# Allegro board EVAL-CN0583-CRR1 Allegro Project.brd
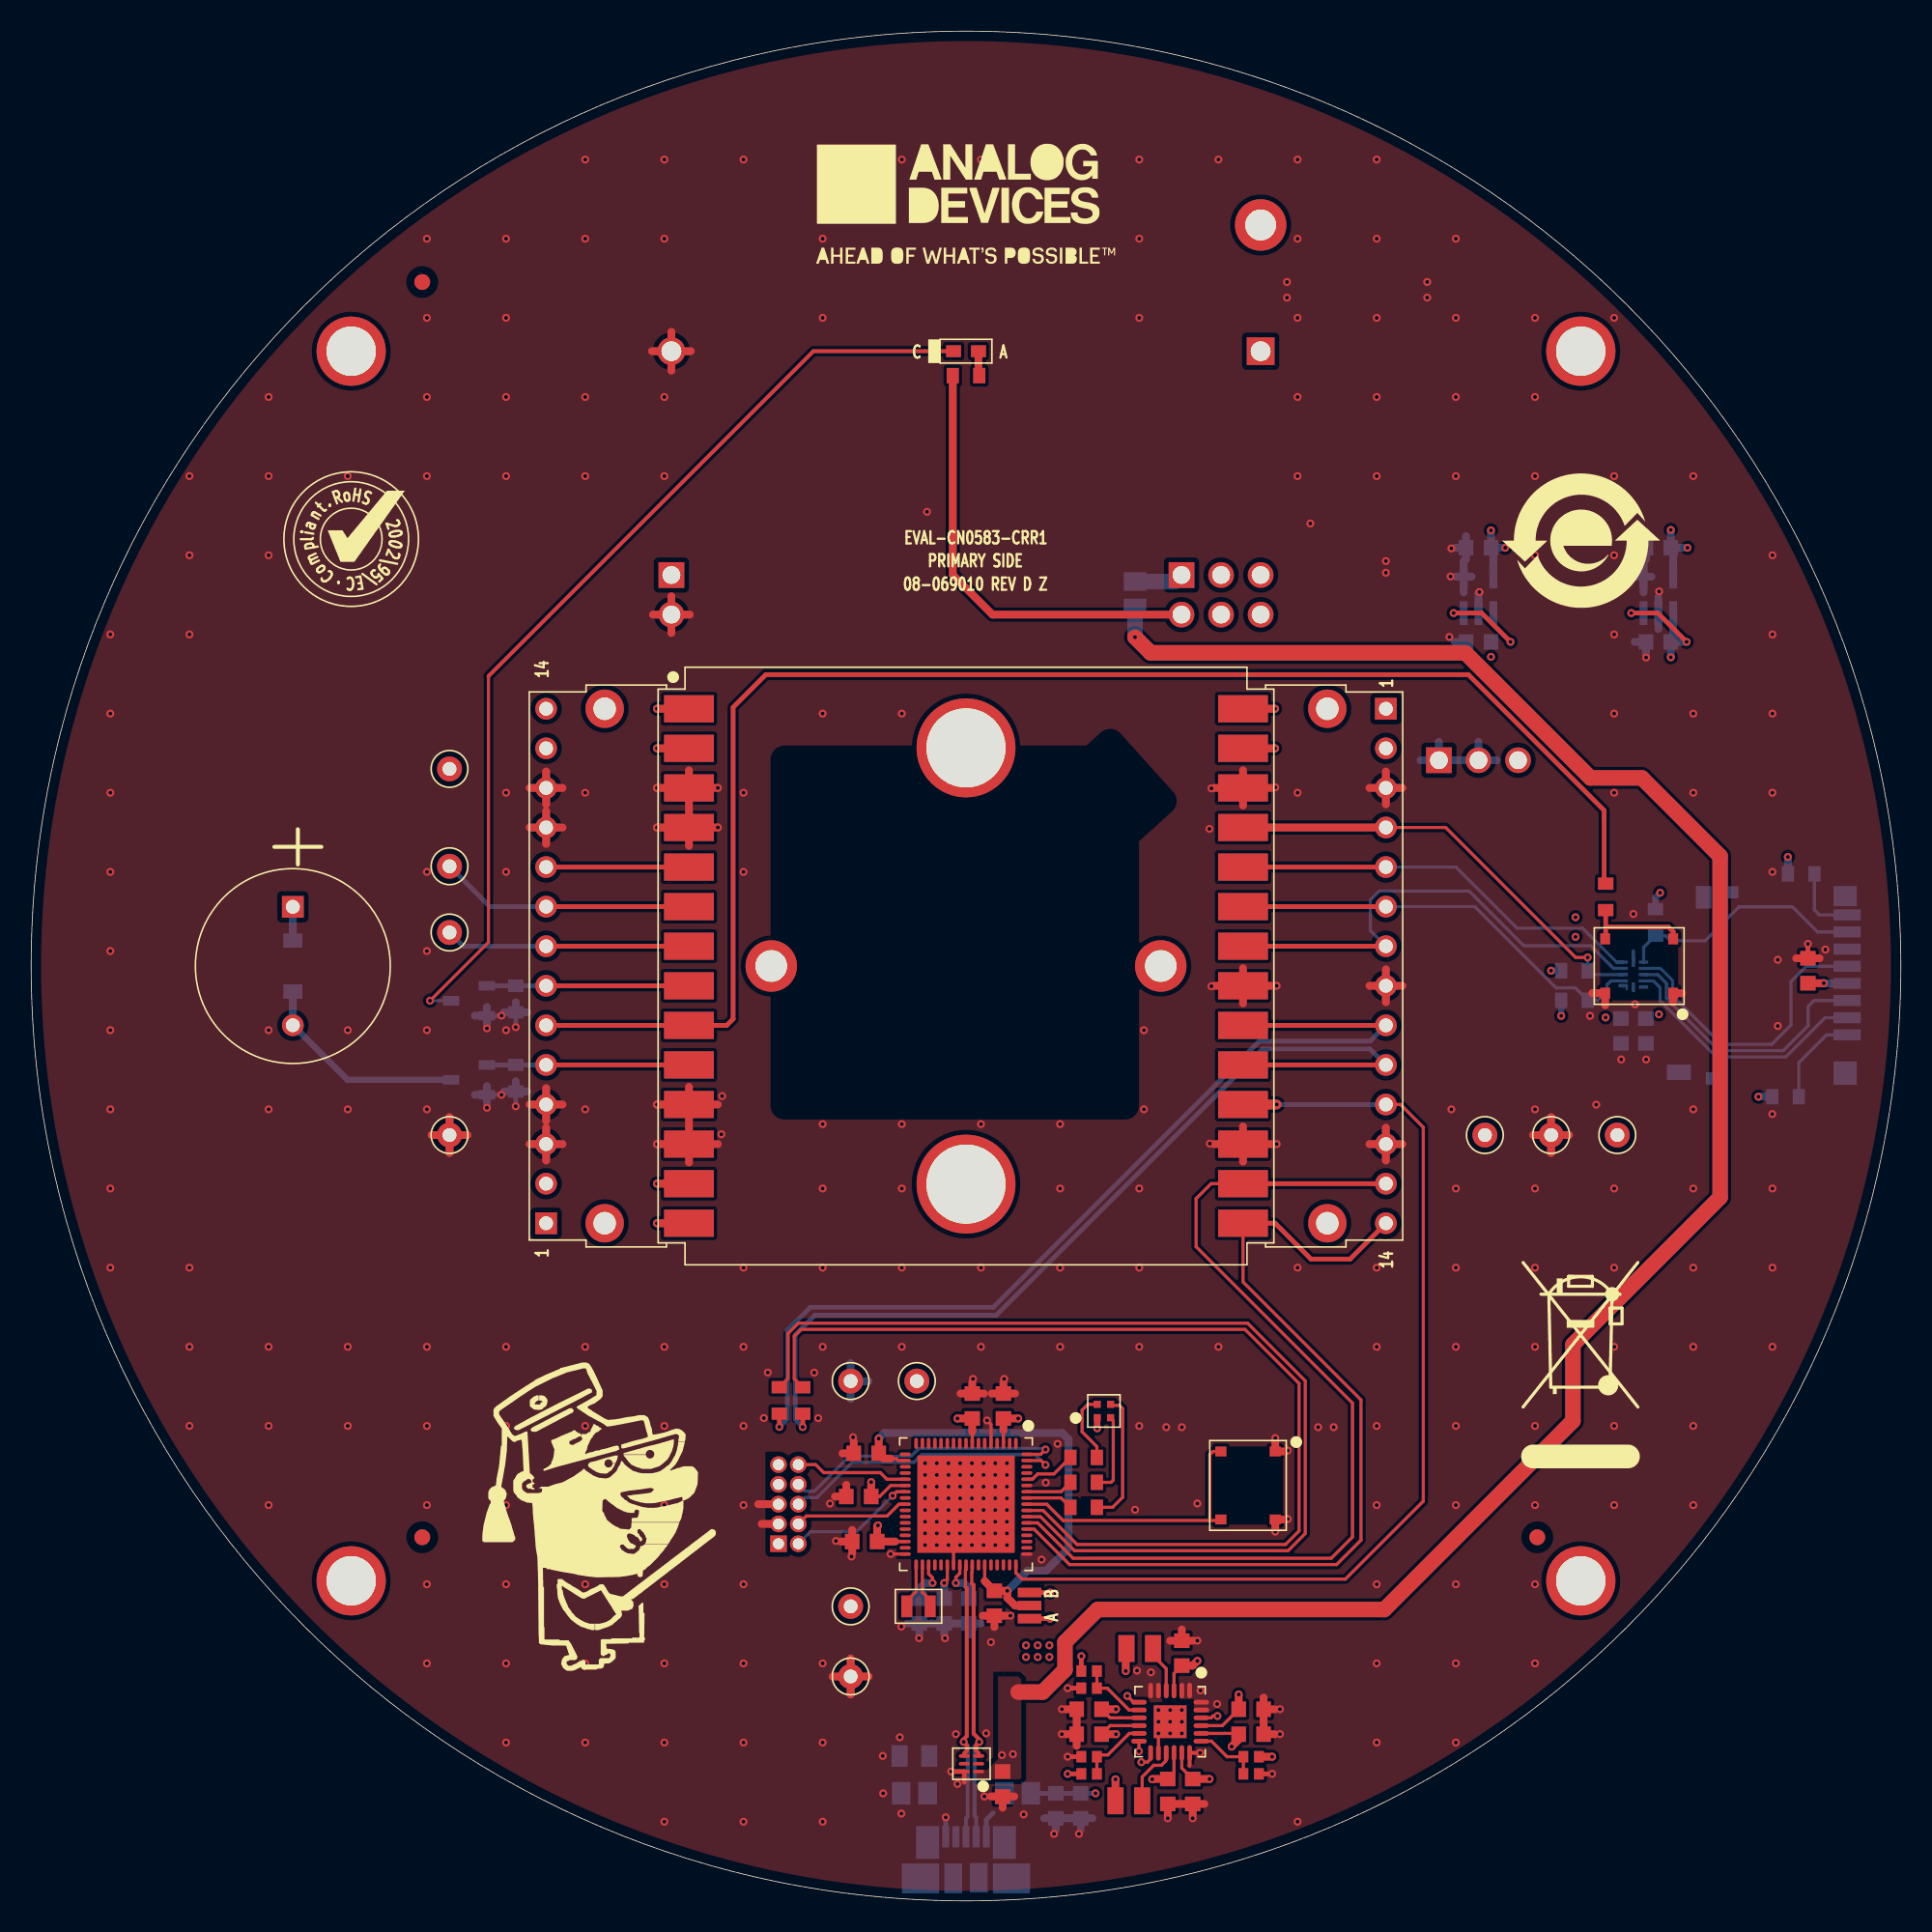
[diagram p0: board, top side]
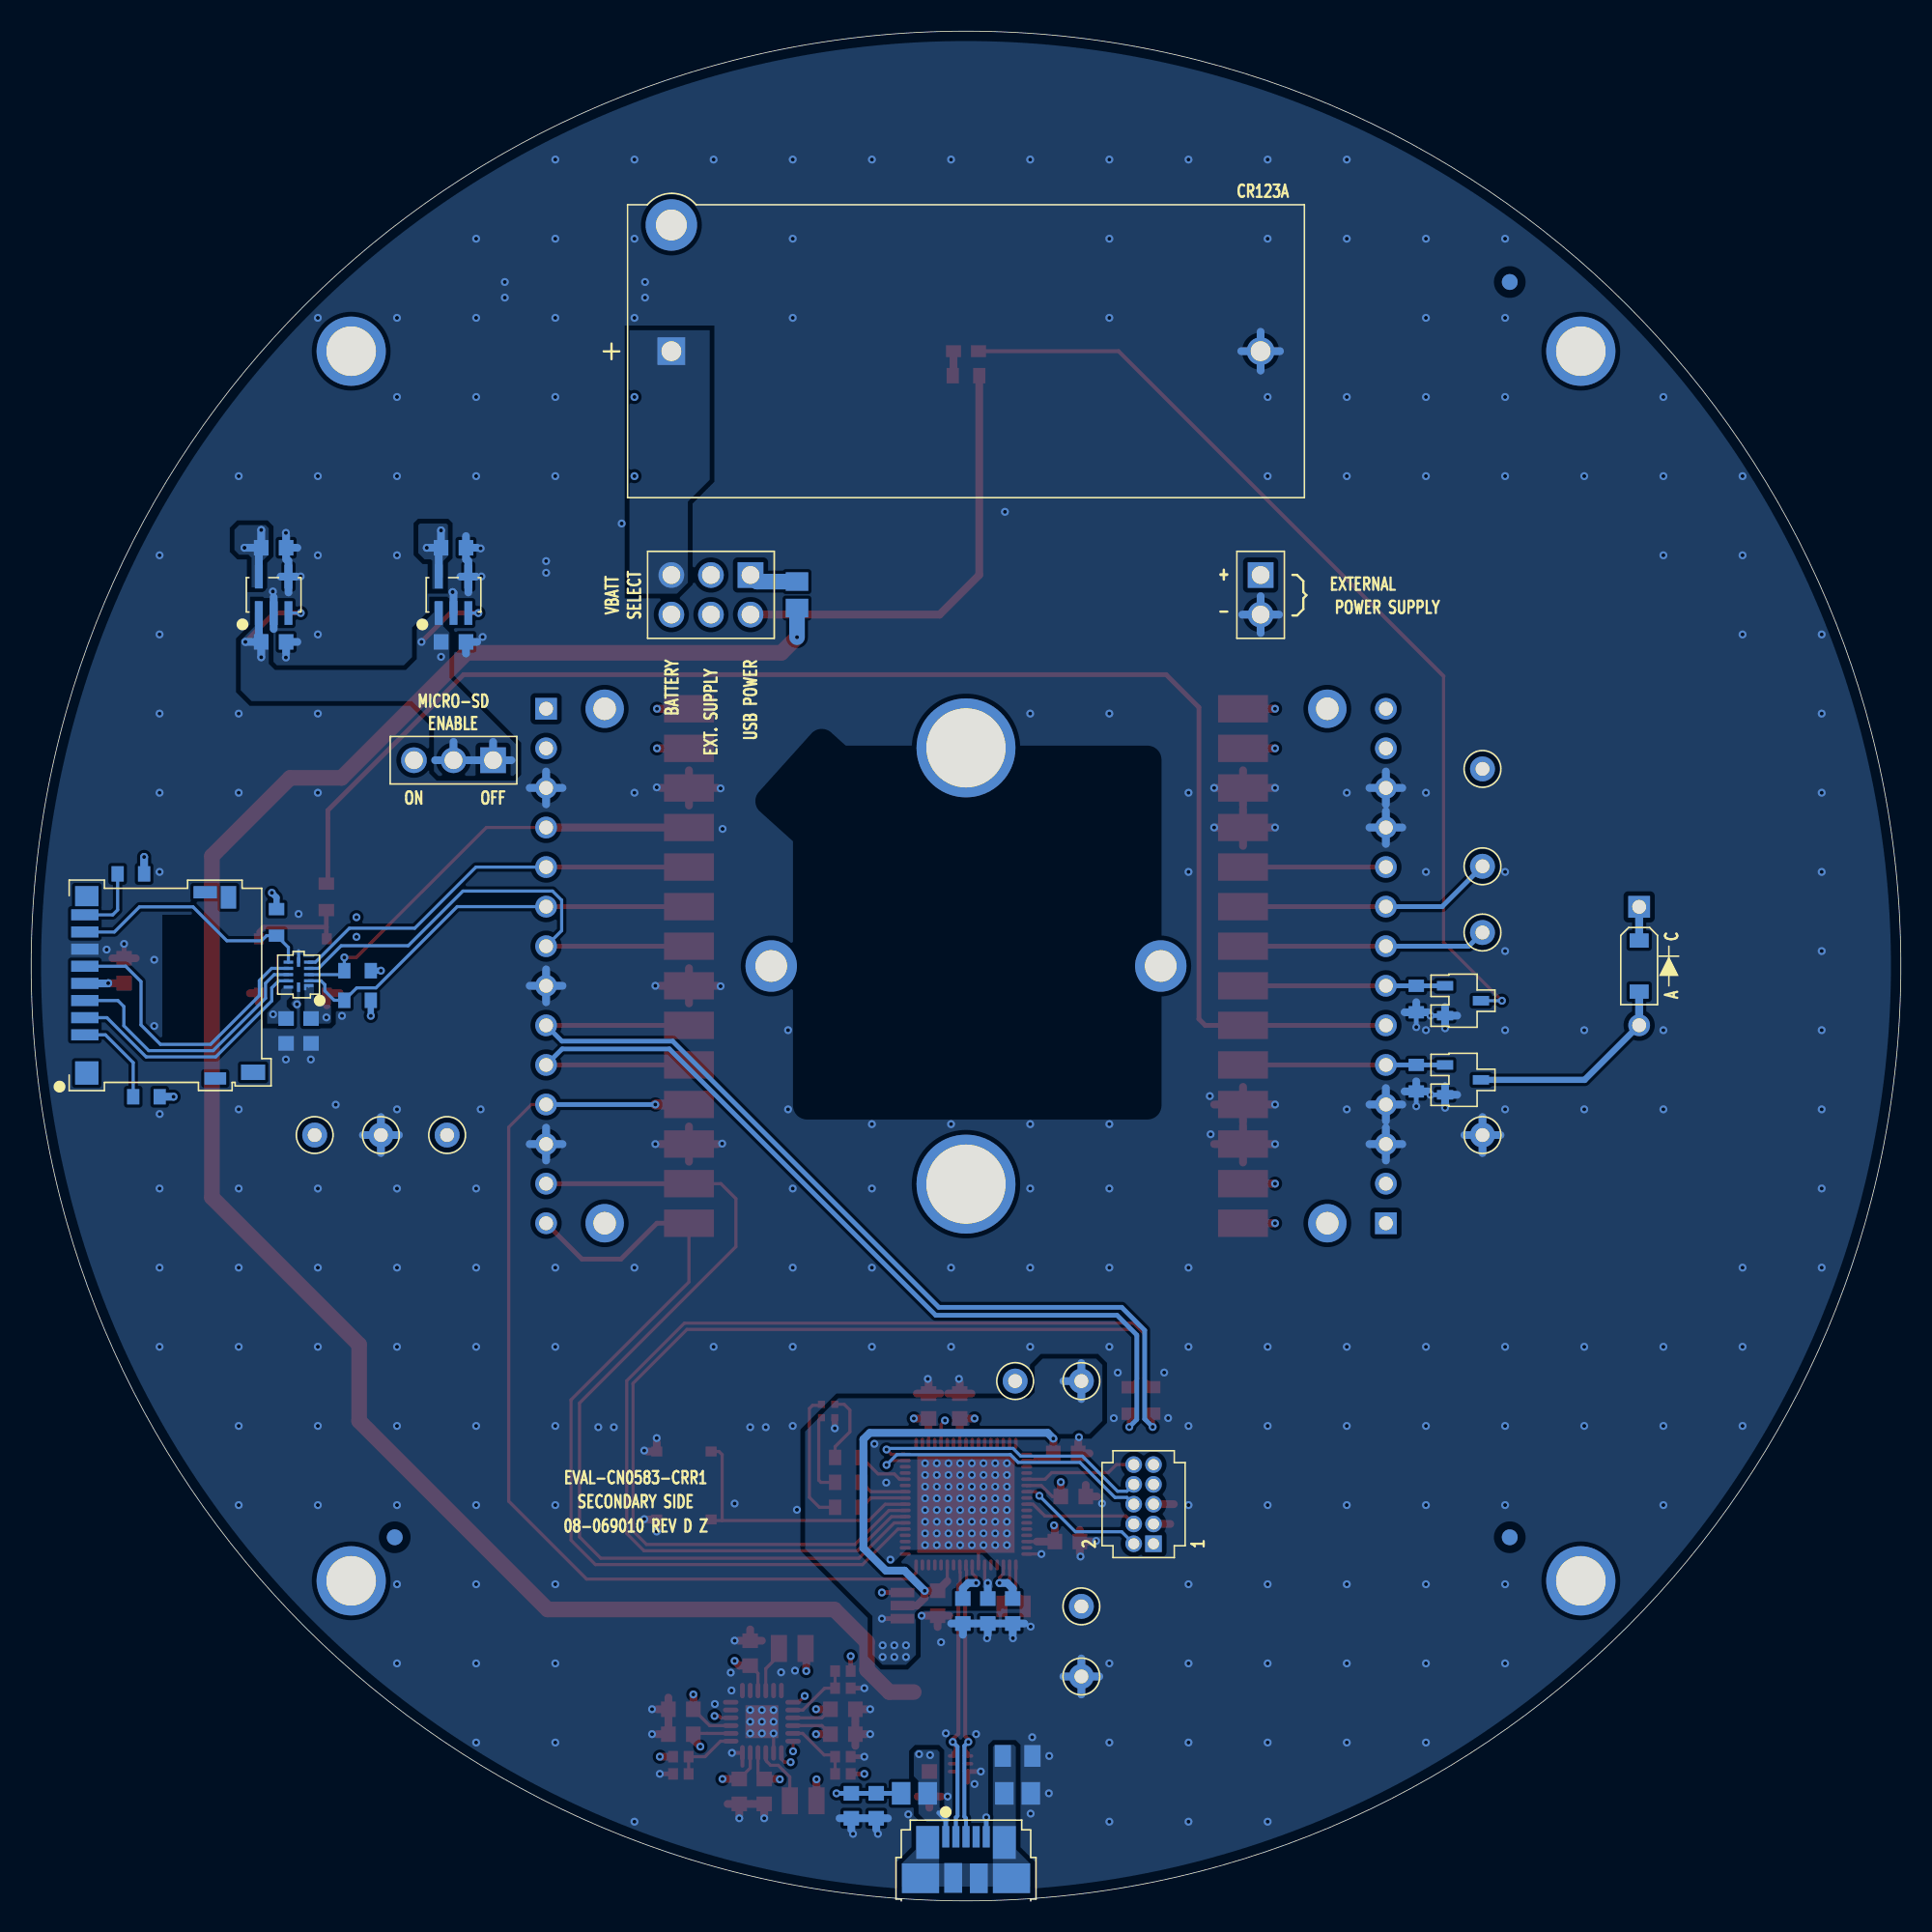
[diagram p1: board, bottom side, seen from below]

Outline 120 x 120 mm; copper layers: TOP, L2_GND, L3_PWR, BOTTOM. Coordinates in mm from the lower left corner of the outline.
Outline path: circle c60,60 r60

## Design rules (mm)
constraint set DEFAULT: 
net group USB_D: nets USB_D+ USB_D-

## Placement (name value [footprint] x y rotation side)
ALARM  APT1608-LSECK-J3-PRV  [LED0603]  60 99.46 0 top
BUZZ  WST-1203UX  [TORAD299D472H315]  16.79 63.8 270 top
C1  0.1uF  [C0603]  102.04 55.83 270 bottom
C2  0.1uF  [C0603]  103.64 55.83 270 bottom
C3  0.1uF  [C0603]  114.04 59.7 90 top
C4  2.2uF  [C0603]  92.89 80.8 180 bottom
C5  2.2uF  [C0603]  92.89 86.84 180 bottom
C6  2.2uF  [C0603]  104.44 80.8 180 bottom
C7  2.2uF  [C0603]  104.44 86.84 180 bottom
C8  0.1uF  [C0603]  62.35 7.5 90 top
C9  0.1uF  [C0603]  65.76 6.1 270 bottom
C10  1UF  [C0603]  67.36 6.1 270 bottom
C11  10UF  [C0603]  73.85 15.9 90 top
C12  10UF  [C0603]  72.95 7.02 270 top
C13  10UF  [C0603]  74.55 7.02 270 top
C14  1UF  [C0603]  78.3 12.3 0 top
C15  4.7UF  [C0603]  78.3 10.7 0 top
C16  4.7UF  [C0603]  67.9 12.3 180 top
C17  4.7UF  [C0603]  67.9 10.7 180 top
C18  1UF  [C0603]  62.4 31.76 90 top
C19  1UF  [C0603]  60.2 18.6 270 bottom
C20  1UF  [C0603]  58.6 18.6 270 bottom
C21  1UF  [C0603]  57 18.6 270 bottom
C22  1UF  [C0603]  53.6 28.72 180 top
C23  1UF  [C0603]  61.82 19.1 270 top
C24  1UF  [C0603]  53.11 25.95 180 top
C25  1UF  [C0603]  53.5 23.06 180 top
C26  1UF  [C0603]  60.4 31.76 90 top
D1  1N4148W-7-F  [SOD123-2]  16.79 60 270 bottom
E1  220OHM  [L0805]  70.85 83.82 90 bottom
E2  220OHM  [L0805]  63.31 6.9 0 bottom
E3  220OHM  [L0805]  56.69 6.9 0 bottom
GND  TP_VIA  [TPC63D35]  26.85 49.15 0 top
GND_SD  TP_VIA  [TPC63D35]  97.55 49.15 0 top
GPIO0  TP_VIA  [TPC63D35]  26.85 66.4 0 top
GPIO1  TP_VIA  [TPC63D35]  26.85 62.15 0 top
JP1  61300621121  [CNHDR2X3H346]  73.83 85.09 0 bottom
JP2  TSW-103-07-F-S  [CNTHMHDR1X3L300W100H343]  90.35 73.21 0 bottom
JP3  3PIN_SOLDER_JUMPER  [JPRSLD03]  64.08 18.95 90 top
L1  1UH  [L0806-2]  71.15 16.2 180 top
L2  1UH  [L0806-2]  70.45 6.42 180 top
M1  EVAL-CN0583-SOMZ  [MEVAL-CN0583-SOMZ]  60 60 270 top
NOREF  -  []  285.25 347.75 0 top
NOREF#2  -  []  60.04 0 0 top
NOREF#3  -  []  47.5 60 0 top
NOREF#4  -  []  94.39 202.59 90 top
NOREF#5  -  []  93.27 32.9 0 top
NOREF#6  -  []  94.39 202.59 90 top
NOREF#7  -  []  20.54 20.54 0 top
NOREF#8  -  []  33.05 25.46 0 top
NOREF#9  -  []  72.04 203.09 0 top
NOREF#10  -  [unnamed#2]  25.1 103.9 0 top
NOREF#11  -  []  72.54 202.59 90 top
NOREF#12  -  []  20.54 20.54 0 top
NOREF#13  -  []  -95.75 -115.8 0 top
NOREF#14  -  []  -34.79 255.04 0 top
NOREF#15  -  []  47.5 60 0 top
NOREF#16  -  []  33.85 33.65 270 top
NOREF#17  -  []  159.5 59.9 0 top
NOREF#18  -  [unnamed#2]  20.54 99.46 0 top
NOREF#19  -  [unnamed#2]  25.1 23.33 0 top
NOREF#20  -  []  27.08 110.16 0 top
NOREF#21  -  [unnamed#2]  96.67 23.33 0 top
NOREF#22  -  []  106.1 33.15 0 top
NOREF#23  -  []  134.25 200.19 0 top
NOREF#24  -  []  -95.75 -115.8 0 top
NOREF#25  -  []  60 0 90 top
NOREF#26  -  []  47.5 60 0 top
NOREF#27  -  []  60 108.9 0 top
NOREF#28  -  [unnamed#2]  20.54 20.54 0 top
NOREF#29  -  []  -95.75 -115.8 0 top
NOREF#30  -  []  0 60 0 top
NOREF#31  -  []  93.48 227.06 312 top
NOREF#32  -  []  42.22 41.08 0 top
NOREF#33  -  []  72.04 225.28 0 top
NOREF#34  -  []  72.19 225.63 0 top
NOREF#35  -  [unnamed#2]  99.46 20.54 0 top
NOREF#36  -  []  -44.95 26.44 0 top
NOREF#37  -  []  -95.75 -115.8 0 top
NOREF#38  -  [unnamed#2]  99.46 99.46 0 top
NOREF#39  -  []  47.5 60 0 top
NOREF#40  -  []  72.04 225.28 0 top
NOREF#41  -  []  219.85 165.65 0 top
NOREF#42  -  [unnamed#2]  25.1 23.33 180 bottom
NOREF#43  -  [unnamed#2]  25.1 103.9 180 bottom
NOREF#44  -  [unnamed#2]  96.67 23.33 180 bottom
P1  829-22-014-20-002101  [CNTHMHDRRA1X14L1400W165H100]  33.05 43.49 90 top
P2  829-22-014-20-002101  [CNTHMHDRRA1X14L1400W165H100]  86.95 76.51 270 top
P3  TSW-101-08-F-D  [CNHDR2X1H340]  41.09 85.09 0 bottom
P4  1129  [SKTKEY1129]  78.91 99.46 180 bottom
P5  114-00841-68  [CNAMP114-00841-68]  111.18 58.76 90 bottom
P6  47346-0001  [CNMOLEX47346-0001]  60 1.8 180 bottom
P7  FTSH-105-01-L-D-K  [CNTHMHDR2X5L250W200H229]  48.6 25.46 90 bottom
Q1  BSS806NEH6327XTSA1  [SOT23_B]  28.1 57.77 270 bottom
Q2  BSS806NEH6327XTSA1  [SOT23_B]  28.1 52.69 270 bottom
R1  1K  [R0603]  101.06 64.44 270 top
R2  150K  [R0603]  31.1 57.88 270 bottom
R3  750  [R0603]  60 97.89 0 top
R4  150K  [R0603]  31.1 52.8 270 bottom
R5  51.1K  [R0603]  99.05 57.8 0 bottom
R6  51.1K  [R0603]  99.05 59.7 0 bottom
R7  51.1K  [R0603]  112.6 51.61 0 bottom
R8  51.1K  [R0603]  104.25 62.8 270 bottom
R9  51.1K  [R0603]  113.6 65.91 0 bottom
R10  1MEG  [R0805]  56.69 9.3 180 bottom
R11  76.8K  [R0402]  67.9 8.15 0 top
R12  13.7K  [R0402]  67.9 9.25 180 top
R13  60.4K  [R0402]  67.9 14.75 0 top
R14  23.2K  [R0402]  67.9 13.65 180 top
R15  30.1K  [R0402]  78.3 9.25 180 top
R16  21.5K  [R0402]  78.3 8.15 0 top
R17  1K  [R0603]  67.55 26.86 0 top
R18  1.4K  [R0603]  67.55 25.26 0 top
R19  2.7K  [R0603]  67.55 28.46 0 top
R20  1K  [R0603]  49.52 32.11 270 top
R21  1K  [R0603]  48.02 32.12 270 top
RGB  SML-LX0404SIUPGUSB  [LED0404]  68.85 31.44 0 top
TEST  MCSLPT4644B2PHTR  [SWSML181W173H49]  103.2 60 180 top
U1  NLSV4T3144MUTAG  [UQFN12_2X1_7]  102.84 59.45 90 bottom
U2  ADP162AUJZ-1.8  [TSOT-5]  92.89 83.82 180 bottom
U3  ADP162AUJZ-3.3  [TSOT-5]  104.44 83.82 180 bottom
U4  MAX13202EALT+T  [DFN6_1_5X1H0_8]  60.35 8.8 90 top
U5  ADP5023ACPZ  [QFN24_4X4_PAD2_1X2_1]  73.1 11.5 180 top
U6  MAX32625ITK+  [QFN68_8X8_PAD6_25X6_25]  60 25.46 180 top
UNK1V2  TP_VIA  [TPC63D35]  56.85 33.36 0 top
UNK1V8  TP_VIA  [TPC63D35]  52.6 18.9 0 top
UNK3V3  TP_VIA  [TPC63D35]  52.6 33.36 0 top
UPDATE  MCSLPT4644B2PHTR  [SWSML181W173H49]  78.1 26.66 270 top
VA_SD  TP_VIA  [TPC63D35]  93.3 49.15 0 top
VB_SD  TP_VIA  [TPC63D35]  101.8 49.15 0 top
VBATT  TP_VIA  [TPC63D35]  26.85 72.65 0 top
VSS  TP_VIA  [TPC63D35]  52.6 14.4 0 top
Y1  32.768KHZ  [YSML79W47H24]  56.95 18.9 0 top

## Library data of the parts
ALARM = DIOLED: Tolerance: N/A; User Part Number: UPN; alternate symbols: (LED0603); part number: DIOLED_SM-APT1608-LSECK-J3-PRV,1.8V,N/A,E027396,LED0603; tolerance: N/A
BUZZ = ICWST_1203UX: User Part Number: UPN; Tolerance: N/A; alternate symbols: (TORAD299D472H315); part number: ICWST_1203UX_TH-WST-1203UX,E050821,TORAD299D472H315; tolerance: N/A
C1-C3 C8 C9 = CAP: User Part Number: UPN; Tolerance: 10; alternate symbols: (C0603); part number: CAP_SM-0.1UF,16V,10,E022365,C0603; tolerance: 10
C4-C7 = CAP: User Part Number: UPN; Tolerance: 10; alternate symbols: (C0603); part number: CAP_SM-2.2UF,25V,10,E031885,C0603; tolerance: 10
C10 C14 C18-C26 = CAP: User Part Number: UPN; Tolerance: 10; alternate symbols: (C0603); part number: CAP_SM-1UF,25V,10,E048498,C0603; tolerance: 10
C11-C13 = CAP: User Part Number: UPN; Tolerance: 10; alternate symbols: (C0603); part number: CAP_SM-10UF,16V,10,E058745,C0603; tolerance: 10
C15-C17 = CAP: User Part Number: UPN; Tolerance: 10; alternate symbols: (C0603); part number: CAP_SM-4.7UF,25V,10,E058970,C0603; tolerance: 10
D1 = DIO: User Part Number: UPN; Tolerance: N/A; alternate symbols: (SOD123-2); part number: DIO_SM-1N4148W-7-F,100V,N/A,E018902,SOD123-2; tolerance: N/A
E1-E3 = FERRITE: User Part Number: UPN; Tolerance: 25; alternate symbols: (L0805); part number: FERRITE_SM-220OHM,25,E017491,L0805; tolerance: 25
GND GND_SD GPIO0 GPIO1 UNK1V2 UNK1V8 UNK3V3 VA_SD VB_SD VBATT VSS = NCTESTPAD: Tolerance: N/A; User Part Number: UPN; alternate symbols: (TPC63D35); part number: NCTESTPAD_TH-TP_VIA,E012149,TPC63D35; tolerance: N/A
JP1 = CN6P_JMPRSHRT: User Part Number: UPN; Tolerance: N/A; alternate symbols: (CNHDR2X3H346); part number: CN6P_JMPRSHRT_TH-61300621121,E026603,CNHDR2X3H346; tolerance: N/A
JP2 = CN3P: User Part Number: UPN; Tolerance: N/A; alternate symbols: (CNTHMHDR1X3L300W100H343); part number: CN3P_TH-TSW-103-07-F-S,E030550,CNTHMHDR1X3L300W100H343; tolerance: N/A
JP3 = NC3P_JMPR: Tolerance: N/A; User Part Number: UPN; alternate symbols: (JPRSLD03); part number: NC3P_JMPR_SM-3PIN_SOLDER_JUMPER,E005606,JPRSLD03; tolerance: N/A
L1 L2 = IND: Tolerance: 30; User Part Number: UPN; alternate symbols: (L0806-2); part number: IND_SM-1UH,30,E020011,L0806-2; tolerance: 30
M1 = MOD_EVAL_CN0583_SOMZ: Tolerance: N/A; User Part Number: UPN; alternate symbols: (MEVAL-CN0583-SOMZ); part number: MOD_EVAL_CN0583_SOMZ_SM-EVAL-CN0583-SOMZ,E063345,MEVAL-CN0583-SOMZ; tolerance: N/A
P1 P2 = CN14P: User Part Number: UPN; Tolerance: N/A; alternate symbols: (CNTHMHDRRA1X14L1400W165H100); part number: CN14P_TH-829-22-014-20-002101,E055893,CNTHMHDRRA1X14L1400W165H100; tolerance: N/A
P3 = CN2P: User Part Number: UPN; Tolerance: N/A; alternate symbols: (CNHDR2X1H340); part number: CN2P_TH-TSW-101-08-F-D,E023119,CNHDR2X1H340; tolerance: N/A
P4 = SKTBAT2P: Tolerance: N/A; User Part Number: UPN; alternate symbols: (SKTKEY1129); part number: SKTBAT2P_TH-1129,E061134,SKTKEY1129; tolerance: N/A
P5 = CN10P_2SHLD_V2: Tolerance: N/A; User Part Number: UPN; alternate symbols: (CNAMP114-00841-68); part number: CN10P_2SHLD_V2_SM-114-00841-68,E034453,CNAMP114-00841-68; tolerance: N/A
P6 = CN5P_6GND: User Part Number: UPN; Tolerance: N/A; alternate symbols: (CNMOLEX47346-0001); part number: CN5P_6GND_SM-47346-0001,E023846,CNMOLEX47346-0001; tolerance: N/A
P7 = CN10P: User Part Number: UPN; Tolerance: N/A; alternate symbols: (CNTHMHDR2X5L250W200H229); part number: CN10P_TH-FTSH-105-01-L-D-K,E032644,CNTHMHDR2X5L250W200H229; tolerance: N/A
Q1 Q2 = TRANNMOSFET_V26: User Part Number: UPN; Tolerance: N/A; alternate symbols: (SOT23_B); part number: TRANNMOSFET_V26_SM-BSS806NEH6327XTSA1,E044202,SOT23_B; tolerance: N/A
R1 R17 R20 R21 = RES: User Part Number: UPN; Tolerance: 1; alternate symbols: (R0603); part number: RES_SM-1K,E029591,1/10W,1,R0603; tolerance: 1
R2 R4 = RES: User Part Number: UPN; Tolerance: 1; alternate symbols: (R0603); part number: RES_SM-150K,E003672,1/10W,1,R0603; tolerance: 1
R3 = RES: User Part Number: UPN; Tolerance: 1; alternate symbols: (R0603); part number: RES_SM-750,E029229,1/10W,1,R0603; tolerance: 1
R5-R9 = RES: User Part Number: UPN; Tolerance: 1; alternate symbols: (R0603); part number: RES_SM-51.1K,E026198,1/10W,1,R0603; tolerance: 1
R10 = RES: User Part Number: UPN; Tolerance: 5; alternate symbols: (R0805); part number: RES_SM-1MEG,E033749,1/8W,5,R0805; tolerance: 5
R11 = RES: User Part Number: UPN; Tolerance: 1; alternate symbols: (R0402); part number: RES_SM-76.8K,E006340,1/10W,1,R0402; tolerance: 1
R12 = RES: User Part Number: UPN; Tolerance: 1; alternate symbols: (R0402); part number: RES_SM-13.7K,E054720,1/10W,1,R0402; tolerance: 1
R13 = RES: User Part Number: UPN; Tolerance: 1; alternate symbols: (R0402); part number: RES_SM-60.4K,E022436,1/10W,1,R0402; tolerance: 1
R14 = RES: User Part Number: UPN; Tolerance: 1; alternate symbols: (R0402); part number: RES_SM-23.2K,E036030,1/10W,1,R0402; tolerance: 1
R15 = RES: User Part Number: UPN; Tolerance: 1; alternate symbols: (R0402); part number: RES_SM-30.1K,E010069,1/10W,1,R0402; tolerance: 1
R16 = RES: User Part Number: UPN; Tolerance: 1; alternate symbols: (R0402); part number: RES_SM-21.5K,E017474,1/10W,1,R0402; tolerance: 1
R18 = RES: User Part Number: UPN; Tolerance: 1; alternate symbols: (R0603); part number: RES_SM-1.4K,E048984,1/10W,1,R0603; tolerance: 1
R19 = RES: User Part Number: UPN; Tolerance: 1; alternate symbols: (R0603); part number: RES_SM-2.7K,E028078,1/10W,1,R0603; tolerance: 1
RGB = DIOLED_4P_V3: User Part Number: UPN; Tolerance: N/A; alternate symbols: (LED0404); part number: DIOLED_4P_V3_SM-SML-LX0404SIUPGUSB,N/A,N/A,E015894,LED0404; tolerance: N/A
TEST UPDATE = SWSPST4PIN_B: User Part Number: UPN; Tolerance: N/A; alternate symbols: (SWSML181W173H49); part number: SWSPST4PIN_B_SM-MCSLPT4644B2PHTR,E061419,SWSML181W173H49; tolerance: N/A
U1 = ICNLSV4T3144: User Part Number: UPN; Tolerance: N/A; alternate symbols: (UQFN12_2X1_7); part number: ICNLSV4T3144_SM-NLSV4T3144MUTAG,E061280,UQFN12_2X1_7; tolerance: N/A
U2 = ADP16X_V3: User Part Number: UPN; Tolerance: N/A; alternate symbols: (TSOT-5); part number: ADP16X_V3_SM-ADP162AUJZ-1.8,E024079,TSOT-5; tolerance: N/A
U3 = ADP16X_V3: User Part Number: UPN; Tolerance: N/A; alternate symbols: (TSOT-5); part number: ADP16X_V3_SM-ADP162AUJZ-3.3,E024091,TSOT-5; tolerance: N/A
U4 = ADMAX13202E: User Part Number: UPN; Tolerance: N/A; alternate symbols: (DFN6_1_5X1H0_8); part number: ADMAX13202E_SM-MAX13202EALT+T,E061247,DFN6_1_5X1H0_8; tolerance: N/A
U5 = ADP5023: Tolerance: N/A; User Part Number: UPN; alternate symbols: (QFN24_4X4_PAD2_1X2_1); part number: ADP5023_SM-ADP5023ACPZ,E015738,QFN24_4X4_PAD2_1X2_1; tolerance: N/A
U6 = ICMAX3262X: User Part Number: UPN; Tolerance: N/A; alternate symbols: (QFN68_8X8_PAD6_25X6_25); part number: ICMAX3262X_SM-MAX32625ITK+,E053258,QFN68_8X8_PAD6_25X6_25; tolerance: N/A
Y1 = XTAL: User Part Number: UPN; Tolerance: 20ppm; alternate symbols: (YSML79W47H24); part number: XTAL_SM-32.768KHZ,E047370,YSML79W47H24; tolerance: 20ppm

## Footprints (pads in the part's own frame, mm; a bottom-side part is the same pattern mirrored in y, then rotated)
C0603
  rect 0.94x0.991 smd: 1(-0.8,0) 2(0.8,0)
CNAMP114-00841-68
  rect 1.499x1.499 smd: (-5.626,5.249)
  rect 1.295x1.499 smd: (5.727,5.249)
  rect 0.711x1.753 smd: 1(-3.175,5.374) 2(-2.075,5.374) 3(-0.975,5.374) 4(0.125,5.374) 5(1.225,5.374) 6(2.325,5.374) 7(3.425,5.374) 8(4.525,5.374)
  rect 0.991x1.549 smd: 9(-5.58,-5.425)
  rect 1.448x0.991 smd: 10(5.651,-3.845)
  rect 0.787x1.397 smd: SH1(-5.976,-2.998)
  rect 0.787x1.499 smd: SH2(5.975,-2.35)
CNHDR2X1H340
  rect 1.651x1.651 hole 1.143: 1(0,0)
  round 1.651 hole 1.143: 2(0,2.54)
CNHDR2X3H346
  rect 1.651x1.651 hole 1.143: 1(0,0)
  round 1.651 hole 1.143: 2(0,2.54) 3(2.54,0) 4(2.54,2.54) 5(5.08,0) 6(5.08,2.54)
CNMOLEX47346-0001
  rect 0.457x1.372 smd: 1(-1.3,2.314) 2(-0.65,2.314) 3(0,2.314) 4(0.65,2.314) 5(1.3,2.314)
  rect 1.473x2.108 smd: G1(-2.462,1.946) G2(2.462,1.946)
  rect 2.388x1.905 smd: G3(2.919,-0.35) G6(-2.919,-0.35)
  rect 1.143x1.905 smd: G4(0.822,-0.35) G5(-0.822,-0.33)
CNTHMHDR1X3L300W100H343
  rect 1.651x1.651 hole 1.143: 1(0,0)
  round 1.651 hole 1.143: 2(2.54,0) 3(5.08,0)
CNTHMHDR2X5L250W200H229
  rect 1.067x1.067 hole 0.711: 1(-2.54,-0.635)
  round 1.067 hole 0.711: 2(-2.54,0.635) 3(-1.27,-0.635) 4(-1.27,0.635) 5(0,-0.635) 6(0,0.635) 7(1.27,-0.635) 8(1.27,0.635) 9(2.54,-0.635) 10(2.54,0.635)
CNTHMHDRRA1X14L1400W165H100
  round 2.464 hole 1.448 unplated: (0,-3.759) (33.02,-3.759)
  rect 1.397x1.397 hole 0.889: 1(0,0)
  round 1.397 hole 0.889: 2(2.54,0) 3(5.08,0) 4(7.62,0) 5(10.16,0) 6(12.7,0) 7(15.24,0) 8(17.78,0) 9(20.32,0) 10(22.86,0) 11(25.4,0) 12(27.94,0) 13(30.48,0) 14(33.02,0)
DFN6_1_5X1H0_8
  oval 0.229x0.711 smd: 1(-0.5,-0.46) 2(0,-0.46) 3(0.5,-0.46) 4(0.5,0.46) 5(0,0.46) 6(-0.5,0.46)
JPRSLD03
  rect 0.61x1.524 smd: 1(-0.838,0) 2(0,0) 3(0.838,0)
L0805
  rect 1.194x1.448 smd: 1(-0.85,0) 2(0.85,0)
L0806-2
  rect 1.041x1.727 smd: 1(-0.856,0) 2(0.856,0)
LED0404
  rect 0.457x0.457 smd: 1(-0.429,-0.429) 2(-0.429,0.429) 3(0.429,0.429) 4(0.429,-0.429)
LED0603
  rect 0.965x0.762 smd: A(0.8,0) C(-0.8,0)
MEVAL-CN0583-SOMZ
  round 6.35 hole 5.08 unplated: (-14,0.001) (14,0.001)
  round 3.302 hole 2.032 unplated: (0,12.501) (0,-12.499)
  rect 1.753x3.2 smd: 1(-16.51,-17.78) 2(-13.97,-17.78) 3(-11.43,-17.78) 4(-8.89,-17.78) 5(-6.35,-17.78) 6(-3.81,-17.78) 7(-1.27,-17.78) 8(1.27,-17.78) 9(3.81,-17.78) 10(6.35,-17.78) 11(8.89,-17.78) 12(11.43,-17.78) 13(13.97,-17.78) 14(16.51,-17.78) 15(16.51,17.78) 16(13.97,17.78) 17(11.43,17.78) 18(8.89,17.78) 19(6.35,17.78) 20(3.81,17.78) 21(1.27,17.78) 22(-1.27,17.78) 23(-3.81,17.78) 24(-6.35,17.78) 25(-8.89,17.78) 26(-11.43,17.78) 27(-13.97,17.78) 28(-16.51,17.78)
QFN24_4X4_PAD2_1X2_1
  oval 0.305x0.991 smd: 1(-1.25,-2) 2(-0.75,-2) 3(-0.25,-2) 4(0.25,-2) 5(0.75,-2) 6(1.25,-2) 13(1.25,2) 14(0.75,2) 15(0.25,2) 16(-0.25,2) 17(-0.75,2) 18(-1.25,2)
  oval 0.991x0.305 smd: 7(2,-1.25) 8(2,-0.75) 9(2,-0.25) 10(2,0.25) 11(2,0.75) 12(2,1.25) 19(-2,1.25) 20(-2,0.75) 21(-2,0.25) 22(-2,-0.25) 23(-2,-0.75) 24(-2,-1.25)
  rect 2.108x2.108 smd: PAD(0,0)
QFN68_8X8_PAD6_25X6_25
  oval 0.229x0.711 smd: 1(-3.2,-3.901) 2(-2.8,-3.901) 3(-2.4,-3.901) 4(-2,-3.901) 5(-1.6,-3.901) 6(-1.2,-3.901) 7(-0.8,-3.901) 8(-0.4,-3.901) 9(0,-3.901) 10(0.4,-3.901) 11(0.8,-3.901) 12(1.2,-3.901) 13(1.6,-3.901) 14(2,-3.901) 15(2.4,-3.901) 16(2.8,-3.901) 17(3.2,-3.901) 35(3.2,3.901) 36(2.8,3.901) 37(2.4,3.901) 38(2,3.901) 39(1.6,3.901) 40(1.2,3.901) 41(0.8,3.901) 42(0.4,3.901) 43(0,3.901) 44(-0.4,3.901) 45(-0.8,3.901) 46(-1.2,3.901) 47(-1.6,3.901) 48(-2,3.901) 49(-2.4,3.901) 50(-2.8,3.901) 51(-3.2,3.901)
  oval 0.711x0.229 smd: 18(3.901,-3.2) 19(3.901,-2.8) 20(3.901,-2.4) 21(3.901,-2) 22(3.901,-1.6) 23(3.901,-1.2) 24(3.901,-0.8) 25(3.901,-0.4) 26(3.901,0) 27(3.901,0.4) 28(3.901,0.8) 29(3.901,1.2) 30(3.901,1.6) 31(3.901,2) 32(3.901,2.4) 33(3.901,2.8) 34(3.901,3.2) 52(-3.901,3.2) 53(-3.901,2.8) 54(-3.901,2.4) 55(-3.901,2) 56(-3.901,1.6) 57(-3.901,1.2) 58(-3.901,0.8) 59(-3.901,0.4) 60(-3.901,0) 61(-3.901,-0.4) 62(-3.901,-0.8) 63(-3.901,-1.2) 64(-3.901,-1.6) 65(-3.901,-2) 66(-3.901,-2.4) 67(-3.901,-2.8) 68(-3.901,-3.2)
  rect 6.248x6.248 smd: PAD(0,0)
R0402
  rect 0.635x0.737 smd: 1(-0.5,0) 2(0.5,0)
R0603
  rect 0.787x0.991 smd: 1(-0.85,0) 2(0.85,0)
R0805
  rect 1.041x1.397 smd: 1(-0.95,0) 2(0.95,0)
SKTKEY1129
  round 3.302 hole 1.981 unplated: (0,8.1)
  rect 1.778x1.778 hole 1.27: 1(0,0)
  round 1.778 hole 1.27: 2(37.82,0)
SOD123-2
  rect 0.914x1.219 smd: A(1.638,0) C(-1.638,0)
SOT23_B
  rect 0.61x1.041 smd: 1(-0.958,-1.15) 2(0.958,-1.15) 3(0,1.15)
SWSML181W173H49
  rect 0.635x0.711 smd: 1(-2.182,1.744) 2(2.182,1.744) 3(-2.182,-1.744) 4(2.182,-1.744)
TORAD299D472H315
  round 1.397 hole 0.889: N(7.6,0)
  rect 1.397x1.397 hole 0.889: P(0,0)
TPC63D35
  round 1.6 hole 0.889: 1(0,0)
TSOT-5
  rect 0.508x1.524 smd: 1(-0.95,-1.17) 2(0,-1.17) 3(0.95,-1.17) 4(0.95,1.17) 5(-0.95,1.17)
unnamed#2
  round 1.016 smd: (0,0)
UQFN12_2X1_7
  custom 0.102x0.102 smd: 1(-0.8,-0.655)
  rect 0.203x0.61 smd: 2(-0.4,-0.655) 3(0,-0.655) 4(0.4,-0.655) 5(0.8,-0.655) 7(0.8,0.655) 8(0.4,0.655) 9(0,0.655) 10(-0.4,0.655) 11(-0.8,0.655)
  rect 0.61x0.203 smd: 6(0.805,0) 12(-0.805,0)
YSML79W47H24
  rect 0.711x1.397 smd: 1(-0.75,0) 2(0.75,0)

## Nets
1V2_DEBUG: C15.1 C26.1 R15.1 U5.20(VOUT3) U6.8 UNK1V2.1
1V8_DEBUG: C14.1 C16.1 C18.1 C19.1 C21.1 C24.1 C25.1 JP3.3 L1.2(N2) P7.1 R13.1 U5.9 U5.21 U5.22 U6.3 U6.23 U6.32 U6.37 U6.42 UNK1V8.1
1V8_SD: C1.1 C5.1 R5.1 R6.1 U1.1 U2.5(VOUT) VA_SD.1(N1)
3V3_DEBUG: C17.1 C20.1 JP3.1 L2.2(N2) R11.1 RGB.1 U5.10 U6.40 UNK3V3.1
3V3_SD: C2.1 C3.1 C7.1 P5.4 R7.1 R8.1 R9.1 U1.11(VCCB) U3.5(VOUT) VB_SD.1(N1)
GND: C1.2(N2) C2.2(N2) C3.2(N2) C4.2(N2) C5.2(N2) C6.2(N2) C7.2(N2) C8.1 C9.2(N2) C10.2(N2) C11.2(N2) C12.2(N2) C13.2(N2) C14.2(N2) C15.2(N2) C16.2(N2) C17.2(N2) C18.2(N2) C19.2(N2) C20.2(N2) C21.2(N2) C22.2(N2) C23.2(N2) C24.2(N2) C25.2(N2) C26.2(N2) E3.1 GND.1(N1) GND_SD.1(N1) M1.3 M1.4 M1.11 M1.12 M1.17 M1.21 M1.26 P1.3 P1.4 P1.11 P1.12 P2.3 P2.8 P2.12 P3.2(N2) P4.2(N2) P5.6 P6.5 P7.3 P7.5 Q1.2(S) Q2.2(S) R2.2(N2) R4.2(N2) R10.2(N2) R12.2(N2) R14.2(N2) R16.2(N2) TEST.1 TEST.2 U1.6 U1.12 U2.2 U2.4 U3.2 U3.4 U4.6 U5.1 U5.2 U5.5 U5.6 U5.14 U5.18 U5.23 U5.24 U5.PAD U6.5 U6.34 U6.41 U6.52 U6.63 U6.PAD(VSS_6) UPDATE.1 UPDATE.2 VSS.1(N1)
VBATT: BUZZ.P D1.C JP1.2 JP1.4 JP1.6(S6) JP2.3(N3) M1.1 M1.2 M1.13 M1.14 M1.27 M1.28(VBATT_6) P1.1 P1.2 P1.13 P1.14 P2.1 P2.2 R3.1 VBATT.1(N1)
ADPD_GPIO0: GPIO0.1(N1) M1.6 P1.9(N9)
ADPD_GPIO1: GPIO1.1(N1) M1.7 P1.8
ALARM_OUT: M1.10 P1.5 Q2.1 R4.1
B_LED: R18.1 U6.61
BUTTON_IN: M1.9 P1.6 R1.1
G_LED: R17.1 U6.62
LED_OUT: M1.8 P1.7 Q1.1 R2.1
R_LED: R19.1 U6.64
RESET_SOM: M1.18 P2.11 U6.51
SPI_CS_SOM: M1.23 P2.6 R5.2(N2) U1.2
SPI_MISO_SOM: M1.24 P2.5 U1.5
SPI_MOSI_SOM: M1.25 P2.4 R6.2(N2) U1.3
SPI_SCLK_SOM: M1.22 P2.7 U1.4
SRST_DEBUG: P7.10 U6.22
SWDCLK_DEBUG: P7.4 U6.26
SWDCLK_SOM: M1.16 P2.13 U6.57
SWDIO_DEBUG: P7.2 U6.24
SWDIO_SOM: M1.15 P2.14 U6.56
UART_RX_DEBUG: P7.8 U6.68
UART_RX_SOM: M1.20 P2.9(N9) R21.2(N2)
UART_TX_DEBUG: P7.6 U6.67
UART_TX_SOM: M1.19 P2.10 R20.2(N2)
UNNAMED_2_CN2P_I129_N1: JP1.3 P3.1
UNNAMED_2_CN6PJMPRSHRT_I134_S1: E1.2(N2) JP1.1
UNNAMED_2_CN6PJMPRSHRT_I134_S5: JP1.5 P4.1
UNNAMED_2_CN14P_I130_N10: M1.5 P1.10
UNNAMED_2_DIO_I6_P: BUZZ.N(N2) D1.A(P) Q2.3
UNNAMED_2_DIOLED_I54_N: ALARM.C Q1.3
UNNAMED_2_DIOLED_I54_P: ALARM.A(P) R3.2(N2)
UNNAMED_2_RES_I62_N2: R1.2(N2) TEST.3 TEST.4(N4)
UNNAMED_3_ADP16XV3_I15_EN: C4.1 C6.1 JP2.1 JP2.2 U2.1 U2.3 U3.1 U3.3
UNNAMED_3_CN10P2SHLDV2_I6_N1: P5.1 R7.2(N2)
UNNAMED_3_CN10P2SHLDV2_I6_N2: P5.2 U1.10
UNNAMED_3_CN10P2SHLDV2_I6_N3: P5.3 U1.9
UNNAMED_3_CN10P2SHLDV2_I6_N5: P5.5 U1.8
UNNAMED_3_CN10P2SHLDV2_I6_N7: P5.7 R8.2(N2) U1.7
UNNAMED_3_CN10P2SHLDV2_I6_N8: P5.8 R9.2(N2)
UNNAMED_4_ADP5023_I30_AVIN: C9.1 C10.1 C11.1 C12.1 C13.1 E2.2(N2) U5.3 U5.7 U5.12 U5.13 U5.16 U5.17
UNNAMED_4_ADP5023_I30_FB1: R11.2(N2) R12.1 U5.11
UNNAMED_4_ADP5023_I30_FB2: R13.2(N2) R14.1 U5.8
UNNAMED_4_ADP5023_I30_FB3: R15.2(N2) R16.1 U5.19
UNNAMED_4_ADP5023_I30_SW1: L2.1 U5.15
UNNAMED_4_ADP5023_I30_SW2: L1.1 U5.4
UNNAMED_4_CAP_I126_N1: C22.1 C23.1 JP3.2(COM) U6.19 U6.46
UNNAMED_4_CN5P6GND_I82_N10: E3.2(N2) P6.G1 P6.G2 P6.G3 P6.G4(N9) P6.G5 P6.G6 R10.1
UNNAMED_4_DIOLED4PV3_I111_C1: R17.2(N2) RGB.4
UNNAMED_4_DIOLED4PV3_I111_C2: R18.2(N2) RGB.3
UNNAMED_4_DIOLED4PV3_I111_C3: R19.2(N2) RGB.2(C3)
UNNAMED_4_ICMAX3262X_I92_32KIN: U6.35 Y1.1
UNNAMED_4_ICMAX3262X_I92_32KOUT: U6.36 Y1.2(N2)
UNNAMED_4_ICMAX3262X_I92_P3: R21.1 U6.58
UNNAMED_4_ICMAX3262X_I92_P3_1: R20.1 U6.59
UPDATE_FW: U6.60 UPDATE.3 UPDATE.4(N4)
USB_D+: P6.3 U4.4 U6.43
USB_D-: P6.2 U4.3 U6.44
USB_POWER: C8.2(N2) E1.1 E2.1 P6.1 U4.1(VCC)

Pads without a net: P5 9 10 SH1 SH2; P6 4; P7 7 9; U4 2 5; U6 1 2 4 6 7 9 10 11 12 13 14 15 16 17 18 20 21 25 27 28 29 30 31 33 38 39 45 47 48 49 50 53 54 55 65 66

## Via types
v1: diameter 0.508, hole 0.254, TOP to BOTTOM, 452 vias

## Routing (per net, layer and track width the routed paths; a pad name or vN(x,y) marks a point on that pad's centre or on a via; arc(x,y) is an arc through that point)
1V2_DEBUG: length 9.1
  TOP w0.2: 76.6,10.75 77.45,10.75 77.5,10.7
  TOP w0.203: U6.8 60.4,30.1 ; 76.6,10.75 U5.20
  TOP w0.5: 60.4,30.1 C26.1 v1(59.45,30.96) ; v1(77.05,9.9) 77.5,10.35 77.5,10.7 ; R15.1 v1(79.65,9.25)
  L3_PWR w0.5: 56.85,32.21 UNK1V2.1 58,33.36
1V8_DEBUG: length 33.2
  TOP w0.2: C16.1 69.25,11.75 69.94,11.75 ; 55.45,23.06 U6.32 ; C24.1 54.46,25.95 55.16,26.66 56.1,26.66 U6.23
  TOP w0.203: v1(57.85,20.4) 57.85,20.74 57.6,20.99 U6.37 ; 69.94,11.75 U5.9 ; U6.42 59.6,21.02 59.35,20.77 v1(59.35,20.4) ; U5.22 75.73,11.75 75.85,11.86 v1(76.14,11.86) ; U6.3 62.4,30.2 ; U5.21 76.45,11.25 77.5,12.3
  TOP w0.3: R13.1 v1(67.4,15.7) ; JP3.3 v1(65.4,19.79)
  TOP w0.5: 77.5,12.3 v1(77.5,13.25) ; v1(69.62,12.3) 69.62,12.3 C16.1 ; C24.1 v1(53.91,26.87) ; 62.4,30.2 C18.1 v1(63.35,30.96) ; 55.45,23.06 C25.1 54.3,24.04 v1(54.35,24.1) ; v1(70.25,14.75) 70.25,16.15 70.29,16.2
  L3_PWR w0.5: 47.08,22.92 47.97,22.92 47.97,22.03 ; UNK1V8.1 53.75,18.9 ; UNK1V8.1 51.44,18.9 ; UNK1V8.1 52.6,20.05 ; UNK1V8.1 52.6,17.75
  BOTTOM w0.5: C19.1 60.2,20.05 59.85,20.4 v1(59.35,20.4) ; v1(57.85,20.4) 57.35,20.4 57,20.05 C21.1
1V8_SD: length 10.2
  L3_PWR w0.5: VA_SD.1 93.3,50.3 ; VA_SD.1 93.3,48 ; VA_SD.1 92.15,49.15 ; VA_SD.1 94.46,49.15
  BOTTOM w0.4: R6.1 v1(97.55,59.7) ; R5.1 v1(98.2,56.8)
  BOTTOM w0.5: C5.1 v1(94.61,86.84) ; C5.1 v1(93.69,87.96) ; C5.1 93.84,86.69 U2.5
  vias: v1(99.12,63.13) v1(99.12,61.87) v1(101.05,56.7)
3V3_DEBUG: length 13.5
  TOP w0.203: C17.1 69.25,11.25 U5.10 ; U6.40 58.8,20.6 v1(58.6,20.4)
  TOP w0.3: R11.1 v1(66.52,8.15) ; JP3.1 v1(65.4,18.11)
  TOP w0.4: RGB.1 v1(68.42,30.33)
  TOP w0.5: v1(69.59,7.8) 69.59,6.42 L2.2 ; C17.1 v1(69.62,10.7)
  BOTTOM w0.5: C20.1 v1(58.6,20.4) ; UNK3V3.1 53.75,33.36 ; UNK3V3.1 52.6,34.51 ; UNK3V3.1 52.6,32.21
  vias: v1(63.85,16.4) v1(63.85,15.65) v1(64.6,16.4) v1(64.6,15.65) v1(65.35,16.4) v1(65.35,15.65)
3V3_SD: length 13.3
  TOP w0.5: C3.1 v1(115.05,58.9)
  L3_PWR w0.5: VB_SD.1 102.96,49.15 ; VB_SD.1 101.8,50.3 ; VB_SD.1 101.8,48
  BOTTOM w0.4: v1(104.55,64.7) 104.25,64.4 R8.1
  BOTTOM w0.5: v1(115.05,58.9) 115.07,58.88 P5.4 ; C7.1 105.39,86.69 U3.5 ; C7.1 v1(106.31,86.84) ; C7.1 v1(105.24,87.98) ; R7.1 v1(110.86,51.61) ; R9.1 v1(112.75,67)
  vias: v1(104.47,56.9)
GND: length 340
  TOP w0.2: U6.41 59.2,22.37 59.63,22.8 v1(59.63,22.83)
  TOP w0.203: U6.34 v1(55.16,22.26) ; U6.5 61.6,30.58 v1(61.35,30.83) ; U5.14 v1(72.35,10.75)
  TOP w0.25: v1(75.02,9.5) U5.18 74.35,8.67
  TOP w0.3: R16.2 v1(79.65,8.15) ; v1(114.04,61.42) C3.2 ; 59.89,7.61 U4.6 v1(59.05,8.3) ; R14.2 v1(66.52,13.65) ; R12.2 v1(66.52,9.25)
  TOP w0.5: 86.95,57.68 P2.8 ; P2.8 85.9,58.73 ; P2.8 86.95,59.78 ; P2.8 88,58.73 ; C26.2 61.15,32.56 ; C26.2 60.4,33.28 ; C26.2 59.65,32.56 ; GND_SD.1 97.55,50.3 ; GND_SD.1 97.55,48 ; GND_SD.1 98.71,49.15 ; GND_SD.1 96.4,49.15 ; GND.1 28,49.15 ; GND.1 25.7,49.15 ; GND.1 26.85,50.3 ; GND.1 26.85,48 ; P3.2 41.09,83.73 ; P3.2 39.91,82.55 ; P3.2 42.27,82.55 ; P3.2 41.09,81.37 ; 66.38,12.3 C16.2 67.1,11.55 ; 33.05,67.84 P1.11 ; P1.11 33.05,69.94 ; P1.11 32,68.89 ; P1.11 34.1,68.89 ; 62.35,5.98 C8.1 ; C8.1 63.1,6.7 ; C8.1 61.6,6.7 ; C18.2 62.4,33.28 ; C18.2 63.15,32.56 ; C18.2 61.65,32.56 ; C23.2 62.57,18.3 ; C23.2 61.82,17.58 ; C23.2 61.07,18.3 ; 85.9,71.43 P2.3 ; P2.3 86.95,70.38 ; P2.3 88,71.43 ; P2.3 86.95,72.48 ; P1.12 34.1,71.43 ; P1.12 33.05,70.38 ; P1.12 32,71.43 ; P1.12 33.05,72.48 ; 66.38,10.7 C17.2 ; C17.2 67.1,11.44 ; C17.2 67.1,9.95 ; 52.07,28.72 C22.2 52.8,29.47 ; 77.78,57.6 M1.21 ; M1.21 77.78,59.86 ; M1.21 79.63,58.73 ; M1.21 75.93,58.73 ; VSS.1 52.6,15.55 ; VSS.1 53.75,14.4 ; VSS.1 51.44,14.4 ; VSS.1 52.6,13.25 ; 100.2,58.25 100.2,58.25 TEST.2 101.02,57.48 ; 32,51.11 P1.4 ; P1.4 34.1,51.11 ; P1.4 33.05,52.16 ; P1.4 33.05,50.06 ; M1.26 79.63,71.43 ; M1.26 77.78,72.56 ; M1.26 75.93,71.43 ; M1.26 77.78,70.3 ; 114.78,60.5 C3.2 113.29,60.5 ; M1.17 79.63,48.57 ; M1.17 75.93,48.57 ; M1.17 77.78,47.44 ; M1.17 77.78,49.7 ; 42.22,49.78 M1.12 ; M1.12 44.07,48.57 ; M1.12 42.22,47.39 ; 79.84,23.91 UPDATE.2 80.45,24.48 ; 39.85,99.46 P4.2 ; P4.2 41.09,98.22 ; P4.2 41.09,100.7 ; P4.2 42.33,99.46 ; M1.11 42.22,49.98 ; M1.11 44.07,51.11 ; M1.11 42.22,52.24 ; 105.96,58.25 TEST.1 105.39,57.64 ; 42.22,70.1 M1.4 ; M1.4 v1(44.07,68.89) ; M1.4 42.22,67.71 ; 73.8,6.22 C13.2 ; C13.2 74.55,5.5 ; C13.2 75.3,6.22 ; 79.1,11.44 C15.2 79.82,10.7 ; P2.12 88,48.57 ; P2.12 85.9,48.57 ; P2.12 86.95,49.62 ; P2.12 86.95,47.52 ; 79.1,11.55 C14.2 ; C14.2 79.82,12.3 ; C14.2 79.1,13.04 ; 79.84,29.41 UPDATE.1 80.45,28.84 ; M1.3 v1(44.07,71.43) ; M1.3 42.22,72.56 ; M1.3 42.22,70.3 ; P1.3 34.1,48.57 ; P1.3 33.05,47.52 ; P1.3 33.05,49.62 ; P1.3 32,48.57 ; C11.2 73.85,17.42 ; C11.2 73.1,16.7 ; C11.2 74.6,16.7 ; P7.3 46.89,24.19 ; 72.95,5.5 C12.2 73.7,6.22 ; 51.97,23.06 C25.2 ; C25.2 52.7,22.31 ; C25.2 52.7,23.81 ; 52.31,26.7 C24.2 51.59,25.95 ; P7.5 46.66,25.46
  TOP w0.508: M1.11 v1(40.17,51.11) ; M1.12 v1(40.17,48.57) ; M1.3 v1(40.17,71.43) ; M1.4 v1(40.17,68.89)
  L2_GND w0.5: P1.4 34.1,51.11 ; P1.4 33.05,52.16 ; P1.4 33.05,50.06 ; P1.4 32,51.11 ; 25.7,49.15 GND.1 ; GND.1 26.85,50.3 ; GND.1 28,49.15 ; GND.1 26.85,48 ; 51.44,14.4 VSS.1 ; VSS.1 52.6,13.25 ; VSS.1 52.6,15.55 ; VSS.1 53.75,14.4 ; GND_SD.1 97.55,50.3 ; GND_SD.1 97.55,48 ; GND_SD.1 96.4,49.15 ; GND_SD.1 98.71,49.15 ; 33.05,70.38 P1.12 ; P1.12 34.1,71.43 ; P1.12 33.05,72.48 ; P1.12 32,71.43 ; 86.95,70.38 P2.3 ; P2.3 86.95,72.48 ; P2.3 88,71.43 ; P2.3 85.9,71.43 ; P1.11 33.05,69.94 ; P1.11 32,68.89 ; P1.11 34.1,68.89 ; P1.11 33.05,67.84 ; 32,48.57 P1.3 ; P1.3 34.1,48.57 ; P1.3 33.05,49.62 ; P1.3 33.05,47.52 ; P2.12 86.95,49.62 ; P2.12 85.9,48.57 ; P2.12 88,48.57 ; P2.12 86.95,47.52 ; 41.09,98.22 P4.2 ; P4.2 42.33,99.46 ; P4.2 39.85,99.46 ; P4.2 41.09,100.7 ; P3.2 41.09,83.73 ; P3.2 39.91,82.55 ; P3.2 42.27,82.55 ; P3.2 41.09,81.37 ; 86.95,57.68 P2.8 ; P2.8 86.95,59.78 ; P2.8 85.9,58.73 ; P2.8 88,58.73
  L3_PWR w0.5: GND_SD.1 97.55,50.3 ; GND_SD.1 96.4,49.15 ; GND_SD.1 97.55,48 ; GND_SD.1 98.71,49.15 ; 41.09,98.22 P4.2 ; P4.2 39.85,99.46 ; P4.2 42.33,99.46 ; P4.2 41.09,100.7 ; P1.4 33.05,52.16 ; P1.4 32,51.11 ; P1.4 34.1,51.11 ; P1.4 33.05,50.06 ; 86.95,70.38 P2.3 ; P2.3 85.9,71.43 ; P2.3 86.95,72.48 ; P2.3 88,71.43 ; 33.05,70.38 P1.12 ; P1.12 34.1,71.43 ; P1.12 32,71.43 ; P1.12 33.05,72.48 ; P1.3 34.1,48.57 ; P1.3 33.05,49.62 ; P1.3 32,48.57 ; P1.3 33.05,47.52 ; P2.12 86.95,49.62 ; P2.12 86.95,47.52 ; P2.12 88,48.57 ; P2.12 85.9,48.57 ; 85.9,58.73 P2.8 ; P2.8 88,58.73 ; P2.8 86.95,59.78 ; P2.8 86.95,57.68 ; 52.6,13.25 VSS.1 ; VSS.1 53.75,14.4 ; VSS.1 51.44,14.4 ; VSS.1 52.6,15.55 ; 26.85,48 GND.1 ; GND.1 25.7,49.15 ; GND.1 26.85,50.3 ; GND.1 28,49.15 ; P1.11 34.1,68.89 ; P1.11 33.05,67.84 ; P1.11 32,68.89 ; P1.11 33.05,69.94
  BOTTOM w0.2: 102.84,60.98 U1.6
  BOTTOM w0.3: R4.2 v1(31.1,51) ; Q2.2 v1(30.19,51.73) ; R2.2 v1(31.1,56.08) ; Q1.2 v1(30.19,56.81) ; P6.5 v1(58.7,5.36)
  BOTTOM w0.5: P1.3 33.05,49.62 ; P1.3 32,48.57 ; P1.3 33.05,47.52 ; P1.3 34.1,48.57 ; P2.8 88,58.73 ; P2.8 85.9,58.73 ; P2.8 86.95,57.68 ; P2.8 86.95,59.78 ; 91.94,84.99 92.45,84.99 ; 91.94,84.99 91.44,84.99 ; 91.94,84.99 91.94,83.98 ; 91.94,84.99 91.94,86.01 ; 92.09,86.09 C5.2 ; C5.2 91.37,86.84 ; C5.2 92.09,87.59 ; P2.3 86.95,72.48 ; P2.3 86.95,70.38 ; P2.3 88,71.43 ; P2.3 85.9,71.43 ; 51.44,14.4 VSS.1 ; VSS.1 53.75,14.4 ; VSS.1 52.6,13.25 ; VSS.1 52.6,15.55 ; 65.76,4.58 C9.2 ; C9.2 65.01,5.3 ; C9.2 66.51,5.3 ; 28.48,56.81 Q1.2 ; Q1.2 29.25,56.26 ; Q1.2 29.25,57.37 ; 59.45,17.8 C19.2 ; C19.2 60.95,17.8 ; C19.2 60.2,17.08 ; P2.12 86.95,49.62 ; P2.12 88,48.57 ; P2.12 86.95,47.52 ; P2.12 85.9,48.57 ; 33.05,50.06 P1.4 ; P1.4 34.1,51.11 ; P1.4 33.05,52.16 ; P1.4 32,51.11 ; GND.1 26.85,50.3 ; GND.1 28,49.15 ; GND.1 26.85,48 ; GND.1 25.7,49.15 ; R2.2 31.85,57.03 ; R2.2 30.35,57.03 ; R2.2 31.1,57.68 ; C7.2 103.64,87.59 ; C7.2 102.91,86.84 ; C7.2 103.64,86.09 ; 56.25,17.8 C21.2 ; C21.2 57,17.08 ; C21.2 57.75,17.8 ; U2.2 92.89,83.94 v1(92.95,84) ; P4.2 42.33,99.46 ; P4.2 41.09,100.7 ; P4.2 39.85,99.46 ; P4.2 41.09,98.22 ; 32,71.43 P1.12 ; P1.12 33.05,72.48 ; P1.12 33.05,70.38 ; P1.12 34.1,71.43 ; 96.4,49.15 GND_SD.1 ; GND_SD.1 97.55,48 ; GND_SD.1 97.55,50.3 ; GND_SD.1 98.71,49.15 ; 102.91,80.8 C6.2 103.64,80.05 ; R4.2 31.85,51.95 ; R4.2 31.1,52.6 ; R4.2 30.35,51.95 ; P3.2 41.09,83.73 ; P3.2 39.91,82.55 ; P3.2 42.27,82.55 ; P3.2 41.09,81.37 ; 28.48,51.73 Q2.2 ; Q2.2 29.25,51.18 ; Q2.2 29.25,52.29 ; 92.09,80.05 C4.2 91.37,80.8 ; U3.4 103.49,86.01 ; U3.4 103.99,84.99 ; U3.4 102.98,84.99 ; U3.4 103.49,83.98 ; 104.44,81.64 U3.2 104.44,83.67 ; 67.36,4.58 C10.2 ; C10.2 68.11,5.3 ; C10.2 66.61,5.3 ; P1.11 34.1,68.89 ; P1.11 33.05,67.84 ; P1.11 33.05,69.94 ; P1.11 32,68.89 ; 58.6,17.08 C20.2 ; C20.2 59.35,17.8 ; C20.2 57.85,17.8
  vias: v1(5.08,81.28) v1(5.08,76.2) v1(5.08,71.12) v1(5.08,66.04) v1(5.08,60.96) v1(5.08,55.88) v1(5.08,50.8) v1(5.08,45.72) v1(5.08,40.64) v1(10.16,91.44) v1(10.16,86.36) v1(10.16,81.28) v1(10.16,40.64) v1(10.16,35.56) v1(10.16,30.48) v1(15.24,96.52) v1(15.24,91.44) v1(15.24,86.36) v1(15.24,55.88) v1(15.24,50.8) v1(15.24,35.56) v1(15.24,30.48) v1(15.24,25.4) v1(20.32,91.44) v1(20.32,55.88) v1(20.32,50.8) v1(20.32,35.56) v1(20.32,30.48) v1(25.4,106.68) v1(25.4,101.6) v1(25.4,96.52) v1(25.4,91.44) v1(25.4,66.04) v1(25.4,60.96) v1(25.4,55.88) v1(25.4,50.8) v1(25.4,35.56) v1(25.4,30.48) v1(25.4,25.4) v1(25.4,20.32) v1(25.4,15.24) v1(29.25,56) v1(29.25,50.9) v1(30.48,106.68) v1(30.48,101.6) v1(30.48,96.52) v1(30.48,91.44) v1(30.48,71.12) v1(30.48,66.04) v1(30.48,55.88) v1(30.48,35.56) v1(30.48,30.48) v1(30.48,25.4) v1(30.48,20.32) v1(30.48,15.24) v1(30.48,10.16) v1(35.56,111.76) v1(35.56,106.68) v1(35.56,96.52) v1(35.56,91.44) v1(35.56,71.12) v1(35.56,50.8) v1(35.56,35.56) v1(35.56,30.48) v1(35.56,25.4) v1(35.56,20.32) v1(35.56,15.24) v1(35.56,10.16) v1(40.64,111.76) v1(40.64,106.68) v1(40.64,96.52) v1(40.64,91.44) v1(40.64,35.56) v1(40.64,30.48) v1(40.64,25.4) v1(40.64,20.32) v1(40.64,15.24) v1(40.64,10.16) v1(40.64,5.08) v1(44.35,51.65) v1(44.3,49.2) v1(45.72,111.76) v1(45.72,71.12) v1(45.72,66.04) v1(45.72,40.64) v1(45.72,35.56) v1(45.72,30.48) v1(45.72,25.4) v1(45.72,20.32) v1(45.72,15.24) v1(45.72,10.16) v1(45.72,5.08) v1(47.03,30.99) v1(47.28,33.91) v1(50.26,33.9) v1(50.51,30.98) v1(50.8,111.76) v1(50.8,106.68) v1(50.8,101.6) v1(50.8,76.2) v1(50.8,49.85) v1(50.8,45.72) v1(50.8,40.64) v1(50.8,35.56) v1(50.8,15.24) v1(50.8,10.16) v1(50.8,5.08) v1(51.27,25.5) v1(51.65,23.1) v1(52.65,22.1) v1(52.75,29.75) v1(54.66,9.3) v1(54.68,6.9) v1(55.75,10.5) v1(55.88,111.76) v1(55.88,76.2) v1(55.88,49.85) v1(55.88,45.72) v1(55.88,40.64) v1(55.88,35.56) v1(55.85,17.6) v1(55.85,5.6) v1(56.99,16.86) v1(57.38,28.08) v1(57.38,27.33) v1(57.38,26.58) v1(57.38,25.83) v1(57.38,25.08) v1(57.38,24.33) v1(57.38,23.58) v1(57.38,22.83) v1(57.5,89.15) v1(58.13,28.08) v1(58.13,27.33) v1(58.13,26.58) v1(58.13,25.83) v1(58.13,25.08) v1(58.13,24.33) v1(58.13,23.58) v1(58.13,22.83) v1(58.65,16.85) v1(58.88,28.08) v1(58.88,27.33) v1(58.88,26.58) v1(58.88,25.83) v1(58.88,25.08) v1(58.88,24.33) v1(58.88,23.58) v1(58.88,22.83) v1(59.35,10.7) v1(59.45,7.5) v1(59.63,28.08) v1(59.63,27.33) v1(59.63,26.58) v1(59.63,25.83) v1(59.63,25.08) v1(59.63,24.33) v1(59.63,23.58) v1(60.38,28.08) v1(60.38,27.33) v1(60.38,26.58) v1(60.38,25.83) v1(60.38,25.08) v1(60.38,24.33) v1(60.38,23.58) v1(60.38,22.83) v1(60.45,33.5) v1(60.96,111.76) v1(60.96,49.85) v1(60.96,40.64) v1(60.96,35.56) v1(61.13,28.08) v1(61.13,27.33) v1(61.13,26.58) v1(61.13,25.83) v1(61.13,25.08) v1(61.13,24.33) v1(61.13,23.58) v1(61.13,22.83) v1(61.18,6.7) v1(61.29,10.75) v1(61.6,16.6) v1(61.88,28.08) v1(61.88,27.33) v1(61.88,26.58) v1(61.88,25.83) v1(61.88,25.08) v1(61.88,24.33) v1(61.88,23.58) v1(61.88,22.83) v1(62.45,33.5) v1(62.63,28.08) v1(62.63,27.33) v1(62.63,26.58) v1(62.63,25.83) v1(62.63,25.08) v1(62.63,24.33) v1(62.63,23.58) v1(62.63,22.83) v1(62.85,18.3) v1(63.7,5.55) v1(64.85,21.9) v1(65.12,26.84) v1(65.65,4.3) v1(65.88,29.33) v1(66.04,111.76) v1(66.04,49.85) v1(66.04,45.72) v1(66.04,40.64) v1(66.04,35.56) v1(66.15,12.3) v1(66.15,10.7) v1(67.25,4.3) v1(70.85,25.1) v1(70.98,14.77) v1(71.12,111.76) v1(71.12,106.68) v1(71.12,101.6) v1(71.12,45.72) v1(71.12,40.64) v1(71.12,35.56) v1(71.12,30.48) v1(71.42,55.88) v1(71.42,50.8) v1(71.87,14.67) v1(72.35,12.25) v1(72.35,11.5) v1(72.85,30.4) v1(72.95,5.3) v1(73.1,12.25) v1(73.1,11.5) v1(73.1,10.75) v1(73.85,30.4) v1(73.85,12.25) v1(73.85,11.5) v1(73.85,10.75) v1(74.55,5.3) v1(74.85,25.5) v1(74.85,16.7) v1(75.05,13.5) v1(75.1,14.65) v1(75.62,68.8) v1(75.65,48.6) v1(75.75,71.4) v1(75.75,58.7) v1(76.12,12.63) v1(76.2,111.76) v1(76.2,35.56) v1(79.85,71.47) v1(79.85,29.7) v1(79.85,23.7) v1(79.94,58.73) v1(79.94,48.57) v1(80.15,12.3) v1(80.15,10.7) v1(80.6,103.9) v1(80.6,102.9) v1(80.65,28.9) v1(80.65,24.5) v1(81.28,111.76) v1(81.28,106.68) v1(81.28,101.6) v1(81.28,96.52) v1(81.28,91.44) v1(81.28,71.12) v1(81.28,40.64) v1(81.28,5.08) v1(82.1,88.4) v1(82.6,30.4) v1(83.6,30.4) v1(86.36,111.76) v1(86.36,106.68) v1(86.36,101.6) v1(86.36,96.52) v1(86.36,91.44) v1(86.36,40.64) v1(86.36,35.56) v1(86.36,30.48) v1(86.36,25.4) v1(86.36,20.32) v1(86.36,15.24) v1(86.36,10.16) v1(86.95,85.99) v1(86.95,85.24) v1(89.6,103.9) v1(89.6,102.9) v1(91.02,81.12) v1(91.15,86.8) v1(91.1,85) v1(91.15,50.8) v1(91.44,106.68) v1(91.44,101.6) v1(91.44,96.52) v1(91.44,91.44) v1(91.44,45.72) v1(91.44,40.64) v1(91.44,35.56) v1(91.44,30.48) v1(91.44,25.4) v1(91.44,20.32) v1(91.44,15.24) v1(91.44,10.16) v1(96.52,101.6) v1(96.52,96.52) v1(96.52,91.44) v1(96.52,86.36) v1(96.52,50.8) v1(96.52,45.72) v1(96.52,40.64) v1(96.52,35.56) v1(96.52,30.48) v1(96.52,25.4) v1(96.52,20.32) v1(96.52,15.24) v1(100.05,56.8) v1(100.45,51.1) v1(101.6,101.6) v1(101.6,91.44) v1(101.6,86.36) v1(101.6,81.28) v1(101.6,76.2) v1(101.6,71.12) v1(101.6,45.72) v1(101.6,40.64) v1(101.6,35.56) v1(101.6,30.48) v1(101.6,25.4) v1(102.05,54) v1(102.7,85) v1(102.84,63.34) v1(102.94,57.54) v1(103.65,87.8) v1(103.65,79.8) v1(103.65,54) v1(104.49,84.04) v1(106.68,91.44) v1(106.68,76.2) v1(106.68,71.12) v1(106.68,50.8) v1(106.68,45.72) v1(106.68,40.64) v1(106.68,35.56) v1(106.68,30.48) v1(106.68,25.4) v1(111.76,86.36) v1(111.76,81.28) v1(111.76,76.2) v1(111.76,71.12) v1(111.76,66.04) v1(111.75,50.5) v1(111.76,45.72) v1(111.76,40.64) v1(111.76,35.56) v1(112.1,60.4) v1(112.1,56.15) v1(115.15,61.05)
VBATT: length 89.3
  TOP w0.5: R3.1 59.15,85.1 61.7,82.55 JP1.2
  TOP w0.508: M1.2 v1(40.17,73.97) ; M1.14 v1(40.17,43.49) ; M1.28 v1(79.83,76.51) ; M1.27 v1(79.83,73.97) ; M1.13 v1(40.17,46.03) ; M1.1 v1(40.17,76.51)
  L3_PWR w0.5: 72.65,82.55 JP1.2 ; JP1.2 73.83,81.37 ; JP1.2 75.01,82.55 ; 33.05,42.44 P1.1 ; P1.1 34.1,43.49 ; P1.1 32,43.49 ; P1.1 33.05,44.54 ; 95.43,72.03 JP2.3 ; JP2.3 94.25,73.21 ; JP2.3 95.43,74.39 ; JP2.3 96.61,73.21 ; 76.37,82.55 77.55,82.55 ; 76.37,82.55 75.19,82.55 ; 76.37,82.55 76.37,81.37 ; 32,76.51 P1.14 ; P1.14 33.05,75.46 ; P1.14 33.05,77.56 ; P1.14 34.1,76.51 ; 33.05,44.98 P1.2 ; P1.2 32,46.03 ; P1.2 34.1,46.03 ; 78.91,82.55 80.09,82.55 ; 78.91,82.55 78.91,81.37 ; 78.91,82.55 77.73,82.55 ; 32,73.97 P1.13 ; P1.13 33.05,75.02 ; P1.13 34.1,73.97 ; P2.2 86.95,75.02 ; P2.2 88,73.97 ; P2.2 85.9,73.97 ; 26.85,71.5 VBATT.1 ; VBATT.1 25.7,72.65 ; VBATT.1 28,72.65 ; VBATT.1 26.85,73.8 ; P2.1 86.95,77.56 ; P2.1 86.95,75.46 ; P2.1 88,76.51 ; P2.1 85.9,76.51 ; 15.74,63.8 BUZZ.P ; BUZZ.P 16.79,62.74 ; BUZZ.P 17.85,63.8 ; BUZZ.P 16.79,64.85
  BOTTOM w0.508: D1.C BUZZ.P
ADPD_GPIO0: length 16.4
  TOP w0.305: P1.9 M1.6
  BOTTOM w0.305: GPIO0.1 29.44,63.81 P1.9
ADPD_GPIO1: length 15.7
  TOP w0.305: P1.8 M1.7
  BOTTOM w0.305: GPIO1.1 27.73,61.27 P1.8
ALARM_OUT: length 13
  TOP w0.305: P1.5 M1.10
  BOTTOM w0.305: P1.5 R4.1 Q2.1
B_LED: length 3
  TOP w0.203: R18.1 66.1,25.86 63.9,25.86
BUTTON_IN: length 97.3
  TOP w0.3: R1.1 100.96,65.39 100.96,69.49
  TOP w0.305: 100.96,69.49 100.96,69.99 92.24,78.7 47.15,78.7 45.05,76.6 45.05,56.6 44.64,56.19 M1.9 P1.6
G_LED: length 3
  TOP w0.203: R17.1 66.1,26.26 63.9,26.26 63.9,26.26
LED_OUT: length 13
  TOP w0.305: P1.7 M1.8
  BOTTOM w0.305: Q1.1 R2.1 P1.7
R_LED: length 3.4
  TOP w0.2: 65.64,27.4 R19.1
  TOP w0.203: 63.9,27.06 64.26,27.06 64.29,27.09 64.29,27.09 64.6,27.4 65.64,27.4
RESET_SOM: length 65.1
  TOP w0.203: U6.51 63.2,21.05 63.6,20.65 84.35,20.65 89.35,25.65 89.35,49.65 87.89,51.11 P2.11
  TOP w0.635: M1.18 v1(79.94,51.11)
  BOTTOM w0.305: v1(79.94,51.11) P2.11
SPI_CS_SOM: length 27.6
  TOP w0.305: M1.23 P2.6
  BOTTOM w0.2: P2.6 92.66,63.81 97.87,58.6 99.1,58.6 R5.2 100.55,57.8 101.15,58.4 101.15,58.8 101.4,59.05 U1.2
SPI_MISO_SOM: length 26.9
  TOP w0.305: M1.24 P2.5
  BOTTOM w0.2: U1.5 101.75,60.25 99.58,62.42 95.38,62.42 91.45,66.35 P2.5
SPI_MOSI_SOM: length 28.8
  TOP w0.2: v1(99.9,60.55) 99.13,60.55 90.79,68.89 P2.4
  TOP w0.508: M1.25 P2.4
  BOTTOM w0.2: U1.3 100.15,59.45 R6.2 v1(99.9,60.55)
SPI_SCLK_SOM: length 31.1
  TOP w0.305: M1.22 P2.7
  BOTTOM w0.2: U1.4 101.55,59.85 100.1,61.3 95.8,61.3 92.29,64.81 86.54,64.81 85.95,64.22 85.95,62.27 P2.7
SRST_DEBUG: length 7.3
  TOP w0.2: 50.35,28 P7.10
  TOP w0.203: 50.35,28 50.87,27.48 54.5,27.48 54.92,27.06 U6.22
SWDCLK_DEBUG: length 7.4
  TOP w0.203: U6.26 55.7,25.46 54.94,24.7 49.75,24.7 P7.4
SWDCLK_SOM: length 60.9
  TOP w0.203: 63.9,24.26 64.6,24.26 66.88,21.99 83.44,21.99 84.8,23.35 84.8,31.95 74.77,41.98 74.77,45.07 75.73,46.03 M1.16
  TOP w0.305: P2.13 M1.16
SWDIO_DEBUG: length 8.2
  TOP w0.203: v1(55.29,26) 55.55,26.26 U6.24
  BOTTOM w0.2: 49.24,22.92 50.01,23.69 52.98,23.69 v1(55.29,26)
SWDIO_SOM: length 57.6
  TOP w0.2: 77.78,43.15 M1.15
  TOP w0.203: 77.78,43.15 77.78,39.72 85.35,32.15 85.35,23.15 83.78,21.58 66.64,21.58 64.37,23.86 63.9,23.86
  TOP w0.305: P2.14 84.65,41.19 82.14,41.19 79.84,43.49 M1.15
UART_RX_DEBUG: length 18.5
  TOP w0.2: U6.68 64.79,28.66 v1(65.1,28.97)
  BOTTOM w0.2: v1(65.1,28.97) 65.03,29.04 56.98,29.04 56.48,28.54 52.52,28.54 50.27,26.29 49.67,26.29 P7.8
UART_RX_SOM: length 63
  TOP w0.3: R21.2 v1(48.02,30.42)
  TOP w0.305: M1.20 P2.9
  BOTTOM w0.3: P2.9 85.94,55.18 78.83,55.18 61.74,38.09 50.01,38.09 48.53,36.62 48.53,30.93 v1(48.02,30.42)
UART_TX_DEBUG: length 18.8
  TOP w0.2: 63.9,28.26 64.82,28.26 v1(65.1,27.97)
  BOTTOM w0.2: v1(65.1,27.97) 64.44,28.64 57.15,28.64 56.65,28.14 52.69,28.14 50.44,25.89 49.67,25.89 P7.6
UART_TX_SOM: length 62.1
  TOP w0.3: R20.2 v1(49.52,30.41)
  TOP w0.305: M1.19 P2.10
  BOTTOM w0.3: P2.10 85.92,54.68 79.03,54.68 61.94,37.58 50.31,37.58 49.04,36.32 49.04,30.89 v1(49.52,30.41)
UNNAMED_2_CN2P_I129_N1: length 4.7
  L3_PWR w0.5: 42.27,85.09 P3.1 41.09,86.27 ; 76.37,86.27 76.37,85.09 75.19,85.09
UNNAMED_2_CN6PJMPRSHRT_I134_S1: length 3.2
  BOTTOM w1: JP1.1 73.41,84.67 E1.2
UNNAMED_2_CN14P_I130_N10: length 9.2
  TOP w0.305: P1.10 M1.5
UNNAMED_2_DIO_I6_P: length 13.8
  BOTTOM w0.4: Q2.3 20.3,52.69 BUZZ.N
  BOTTOM w0.508: D1.A BUZZ.N
UNNAMED_2_DIOLED_I54_N: length 62.2
  TOP w0.2: 29.35,78.6 29.35,61.52 v1(25.6,57.77)
  TOP w0.25: ALARM.C 50.21,99.46 29.35,78.6
  BOTTOM w0.2: Q1.3 v1(25.6,57.77)
UNNAMED_2_DIOLED_I54_P: length 1.6
  TOP w0.5: ALARM.A 60.8,97.94 R3.2
UNNAMED_2_RES_I62_N2: length 6.8
  TOP w0.3: 101.06,62.5 105.09,62.5 105.39,62.2 TEST.3 ; 101.06,62.5 101.06,61.77 TEST.4 ; 101.06,62.5 R1.2
UNNAMED_3_ADP16XV3_I15_EN: length 21.2
  TOP w0.3: v1(102.7,82.65) 104.4,82.65 v1(106.25,80.8) ; v1(91.3,82.65) 93.1,82.65 v1(94.95,80.8)
  BOTTOM w0.2: 91.94,82.65 v1(91.3,82.65) ; U3.3 v1(102.7,82.65)
  BOTTOM w0.5: C6.1 105.39,80.95 U3.1 ; C6.1 v1(106.25,80.8) ; C6.1 v1(105.24,79.81) ; 92.89,73.21 94.07,73.21 ; 92.89,73.21 92.89,74.39 ; 92.89,73.21 91.71,73.21 ; JP2.1 91.53,73.21 ; JP2.1 89.17,73.21 ; JP2.1 90.35,74.39
  vias: v1(93.69,79.84)
UNNAMED_3_CN10P2SHLDV2_I6_N1: length 6
  BOTTOM w0.2: P5.1 115.23,55.58 113.45,53.8 113.45,51.61 R7.2
UNNAMED_3_CN10P2SHLDV2_I6_N2: length 16.6
  BOTTOM w0.2: P5.2 115.13,56.68 112.62,54.17 108.15,54.17 104.56,57.76 104.56,58.6 104.11,59.05 U1.10
UNNAMED_3_CN10P2SHLDV2_I6_N3: length 17.7
  BOTTOM w0.2: P5.3 114.43,57.78 114.05,57.4 114.05,56.17 112.45,54.57 108.32,54.57 104.96,57.93 104.96,58.89 104.4,59.45 U1.9
UNNAMED_3_CN10P2SHLDV2_I6_N5: length 19.4
  BOTTOM w0.2: P5.5 113.93,59.98 112.95,59 112.95,56.22 111.7,54.97 108.48,54.97 105.36,58.1 105.36,59.06 104.57,59.85 U1.8
UNNAMED_3_CN10P2SHLDV2_I6_N7: length 16
  BOTTOM w0.2: P5.7 114.66,62.18 113.04,63.8 109.61,63.8 107.44,61.62 105.22,61.62 104.89,61.95 R8.2 103.49,61.19 U1.7
UNNAMED_3_CN10P2SHLDV2_I6_N8: length 4.5
  BOTTOM w0.2: R9.2 114.45,63.6 114.77,63.28 P5.8
UNNAMED_4_ADP5023_I30_AVIN: length 15.6
  TOP w0.2: C12.1 73.35,8.22 73.35,8.8 ; C11.1 73.35,14.6 ; C13.1 73.85,8.52
  TOP w0.203: U5.13 71.85,9.1 71.65,8.9 v1(71.25,8.9) ; v1(71.1,9.6) U5.12 ; 73.35,14.6 U5.3 ; v1(70.35,13.15) 70.75,12.75 U5.7 ; 73.35,8.8 U5.16 ; 73.85,8.52 U5.17
  TOP w0.5: C13.1 v1(75.63,7.82) ; v1(71.95,7.8) 71.97,7.82 C12.1 ; v1(74.85,15.4) 74.55,15.1 C11.1
  BOTTOM w0.305: E2.2 C9.1 C10.1 v1(68.31,6.9)
UNNAMED_4_ADP5023_I30_FB1: length 4.4
  TOP w0.2: R11.2 R12.1 68.51,9.36 69.1,9.36
  TOP w0.203: U5.11 70.48,10.75 69.1,9.36
UNNAMED_4_ADP5023_I30_FB2: length 4.4
  TOP w0.2: 69.1,13.61 69.06,13.65 R14.1 R13.2
  TOP w0.203: U5.8 70.47,12.25 69.1,13.61
UNNAMED_4_ADP5023_I30_FB3: length 4.2
  TOP w0.2: R16.1 R15.2 76.75,9.25 76.65,9.35
  TOP w0.203: U5.19 75.76,10.25 76.65,9.35
UNNAMED_4_ADP5023_I30_SW1: length 4
  TOP w0.2: 71.75,8.4 71.31,7.96 71.31,6.42 L2.1
  TOP w0.203: 71.75,8.4 72.05,8.7 72.54,8.7 72.8,8.96 72.8,9 72.85,9.04 U5.15
UNNAMED_4_ADP5023_I30_SW2: length 3
  TOP w0.203: L1.1 72.01,15.74 72.85,14.9 U5.4
UNNAMED_4_CAP_I126_N1: length 32.2
  TOP w0.203: 55.16,28.38 55.53,28.38 55.65,28.26 U6.19 ; U6.46 61.2,20.52
  TOP w0.5: 61.2,20.52 C23.1 v1(62.65,19.9) 62.65,19.45 63.15,18.95 JP3.2 ; v1(54.4,29.67) C22.1 54.73,28.38 55.16,28.38
  BOTTOM w0.5: v1(54.4,29.67) 54.76,30.03 66.17,30.03 66.58,29.62 66.58,22.64 65.14,21.19 63.95,21.19 v1(62.65,19.9)
UNNAMED_4_DIOLED4PV3_I111_C1: length 5.2
  TOP w0.2: 68.4,26.86 69.31,26.86 69.45,27 69.45,30.84 RGB.4
UNNAMED_4_DIOLED4PV3_I111_C2: length 8.5
  TOP w0.2: RGB.3 69.35,31.8 69.85,31.8 70.05,31.6 70.05,25.9 69.41,25.26 68.4,25.26
UNNAMED_4_DIOLED4PV3_I111_C3: length 4.6
  TOP w0.2: RGB.2 67.82,31.87 67.45,31.5 67.45,30.1 68.4,29.15 68.4,28.46
UNNAMED_4_ICMAX3262X_I92_32KIN: length 2.9
  TOP w0.2: Y1.1 56.2,19.25 56.8,19.85 U6.35
UNNAMED_4_ICMAX3262X_I92_32KOUT: length 2.9
  TOP w0.2: Y1.2 57.7,19.3 57.2,19.8 U6.36
UNNAMED_4_ICMAX3262X_I92_P3: length 67.7
  TOP w0.2: 63.9,24.66 63.91,24.65 64.78,24.65 66.97,22.47 80.67,22.47 81.77,23.57 81.77,33.37 78.07,37.08 49.24,37.08 48.58,36.41 48.58,33.52 R21.1
UNNAMED_4_ICMAX3262X_I92_P3_1: length 65.7
  TOP w0.2: 63.9,25.06 63.91,25.05 64.95,25.05 67.13,22.87 80.51,22.87 81.38,23.74 81.38,33.21 77.91,36.68 49.41,36.68 48.98,36.24 48.98,33.51 R20.1
UPDATE_FW: length 17.9
  TOP w0.2: 76.29,24.41 UPDATE.4
  TOP w0.203: 75.65,24.41 75.65,28.64 75.85,28.84 UPDATE.3 ; 75.65,24.41 66.23,24.41 65.18,25.46 63.9,25.46 63.9,25.46 ; 75.65,24.41 76.29,24.41
USB_D+: length 18.8
  TOP w0.2: 60.05,20.08 59.96,20.17 59.96,21.22 60.01,21.27 60.01,21.55 U6.43
  TOP w0.254: U4.4 59.89,9.47 60.05,9.64 60.05,10 v1(59.85,10.2) 59.85,10.37 60.05,10.57 60.05,20.08
  BOTTOM w0.254: v1(59.85,10.2) 60.11,9.94 60.11,5.41 60,5.3 60,4.11 P6.3
USB_D-: length 18.9
  TOP w0.2: 60.37,20.38 60.37,21.09 60.39,21.11 60.39,21.55 U6.44
  TOP w0.254: U4.3 60.81,9.47 60.65,9.64 60.65,10 v1(60.85,10.2) 60.85,10.37 60.49,10.73 60.49,20.26 60.37,20.38
  BOTTOM w0.254: P6.2 60.65,4.11 60.65,5.35 60.54,5.46 60.54,9.89 v1(60.85,10.2)
USB_POWER: length 131
  TOP w1: 63.35,13.4 64.92,13.4 66.35,14.83 66.35,16.6 68.45,18.7 86.85,18.7 98.95,30.8 98.95,35.7 108.4,45.15 108.4,67.05 103.38,72.07 100.08,72.07 92.05,80.1 71.85,80.1 v1(70.85,81.1)
  BOTTOM w0.305: 61.75,5.65 61.3,5.2 P6.1
  BOTTOM w1: E1.1 v1(70.85,81.1)
  vias: v1(62.3,9.35) v1(63.01,9.41)

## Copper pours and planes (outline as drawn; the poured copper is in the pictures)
1V2_DEBUG on L3_PWR: 75.85,34.15 82.85,27.15 82.85,8.65 81.85,7.65 76.95,7.65 76.75,7.85 76.75,10.1 76.85,10.2 78.85,10.2 79.6,10.95 79.6,26.15 73.6,32.15 61.35,32.15 59.85,30.65 56.3,30.65 55.85,31.1 55.85,34 56,34.15
1V8_DEBUG on L3_PWR: 78.1,17.9 78.1,11.9 77.6,11.4 75.85,11.4 75.6,11.65 75.6,15.23 74.88,15.95 72.48,15.95 69.85,13.33 69.85,11.9 69.75,11.8 66.15,11.8 65.85,12.1 65.85,17.15 65.85,17.15 50.35,17.15 46.35,21.15 46.35,28.65 48.1,30.4 60.1,30.4 61.55,31.85 63.9,31.85 64.35,31.4 64.35,29.15 63.86,28.66 57.18,28.66 56.82,28.3 56.82,21.34 57.26,20.9 60.1,20.9 60.94,20.06 75.94,20.06
1V8_SD on BOTTOM: 102.45,58.7 102.45,56.4 102.35,56.3 100.85,56.3 100.75,56.4 100.75,57.4 100.85,57.5 101.75,57.5 101.85,57.6 101.85,58.7
1V8_SD on BOTTOM: 93.55,84.2 93.55,86 93.25,86.3 93.25,88.3 93.35,88.4 95.05,88.4 95.15,88.3 95.15,86.5 94.75,86.1 94.35,86.1 94.25,86 94.25,84.2
1V8_SD on L3_PWR: 93.45,88.4 96.25,88.4 101.95,82.7 101.95,57.05 95.5,50.6 95.5,48.75 94.45,47.7 92.05,47.7 91.75,48 91.75,54.3 98.65,61.2 98.65,79.7 93.35,85 93.35,88.3
3V3_DEBUG on BOTTOM: 66.01,29.96 66.77,29.2 66.77,22.6 65.5,21.33 64.61,21.33 63.72,22.22 58.97,22.22 58.05,21.3 58.05,18.92 62.83,18.92 63.21,18.53 63.21,15.79 63.85,15.15 65.35,15.15 66.01,15.81 66.01,18.28 70.33,22.6 70.33,30.12 68.19,32.26 55.97,32.26 55.59,32.63 55.59,34.28 55.08,34.8 51.65,34.8 51.25,34.4 51.25,30.8 52.09,29.96
3V3_DEBUG on L3_PWR: 64.85,7.65 68.35,7.65 69,7 70.65,7 70.85,7.2 70.85,8.45 69.85,9.45 69.85,11 69.75,11.1 66.4,11.1 65.6,11.9 65.6,16.65 63.6,16.65 63.6,8.9
3V3_SD on BOTTOM: 103.25,58.7 103.75,58.7 103.98,58.47 103.98,57.87 104.85,57 104.85,56.3 103.35,56.3 103.25,56.4 103.25,57.05 103.6,57.4 103.6,57.78 103.25,58.13
3V3_SD on BOTTOM: 104.95,88.3 106.65,88.3 106.95,88 106.95,86.7 106.65,86.4 106.05,86.4 105.85,86.2 105.85,84.3 105.25,84.3 105.15,84.4 105.15,86 104.75,86.4 104.75,88.1
3V3_SD on L3_PWR: 104.95,88.7 107.25,88.7 108.55,87.4 108.55,73.3 115.45,66.4 115.45,52.4 110.75,47.7 100.85,47.7 100.45,48.1 100.45,49.9 104.25,53.7 104.25,88
GND on TOP: 0.63,60 119.36,60 ; 14 cut-outs
GND on BOTTOM: 0.63,60 119.36,60 ; 2 cut-outs
GND on L2_GND, L3_PWR: 0.63,60 119.36,60
VBATT on L3_PWR: 89.43,71.07 87.35,73.15 69.35,73.15 63.85,78.65 51.1,78.65 45.35,72.9 29.1,72.9 24.1,67.9 24.1,47.15 43.71,47.15 44.92,45.94 44.92,39.08 43.74,37.9 16.6,37.9 14.15,40.35 14.15,74.65 22.58,83.07 89.38,83.07 97.35,75.1 97.35,71.6 96.83,71.07
UNNAMED_2_CN2P_I129_N1 on L3_PWR: 40.05,93.45 77.3,93.45 77.3,84.2 40.05,84.2
UNNAMED_2_CN6PJMPRSHRT_I134_S5 on BOTTOM: 81.6,100.8 81.6,83.9 78.55,83.9 77.85,84.6 77.85,89.8 76.45,91.2 76.45,100.8
UNNAMED_3_ADP16XV3_I15_EN on BOTTOM: 93.55,83.4 93.55,81.8 93.15,81.4 93.15,78.5 88.85,74.2 88.85,72.4 89.05,72.2 93.85,72.2 94.15,72.5 94.15,75.6 95.55,77 105.85,77 106.55,77.7 106.55,80.9 105.65,81.8 105.65,83.4 105.25,83.4 105.15,83.3 105.15,81.4 105.05,81.3 104.85,81.3 104.75,81.2 104.75,79.4 104.35,79 95.95,79 95.25,79.7 95.25,81.6 94.15,82.7 94.15,83.4
UNNAMED_4_ADP5023_I30_AVIN on L3_PWR: 74.6,15.65 72.6,15.65 70.1,13.15 70.1,9.65 71.15,8.6 71.15,7 70.95,6.8 68.8,6.8 68.36,7.24 67.35,7.24 67.1,6.99 67.1,5.9 67.2,5.8 75.45,5.8 75.85,6.2 75.85,10.9 75.35,11.4 75.35,14.9
UNNAMED_4_CN5P6GND_I82_N10 on BOTTOM: 61.73,4.8 61.73,2.4 61.72,2.4 58.27,2.4 58.27,9.88 58.14,10.02 56.94,10.02 56.8,9.88 56.8,3.31 55.89,2.4 55.89,0.91 64.11,0.91 64.11,2.4 63.2,3.31 63.2,4.8
USB_POWER on TOP: 62.05,14.4 62.05,9.1 61.35,8.4 60.55,8.4 60.55,8 60.75,7.8 63.45,7.8 63.55,7.9 63.55,14.2 63.35,14.4
USB_POWER on BOTTOM: 61.05,5.07 61.05,5.35 61.7,6 61.7,9.55 61.85,9.7 63.15,9.7 63.35,9.5 63.35,8 63.05,7.7 63.05,5.6 62.52,5.07

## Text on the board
Ref Des/Assembly Bottom: 1X CR2477 WILL BE INSTALLED IN THE HOLDER | BATTERY ENTRY | MATE ENTRY | C | A
